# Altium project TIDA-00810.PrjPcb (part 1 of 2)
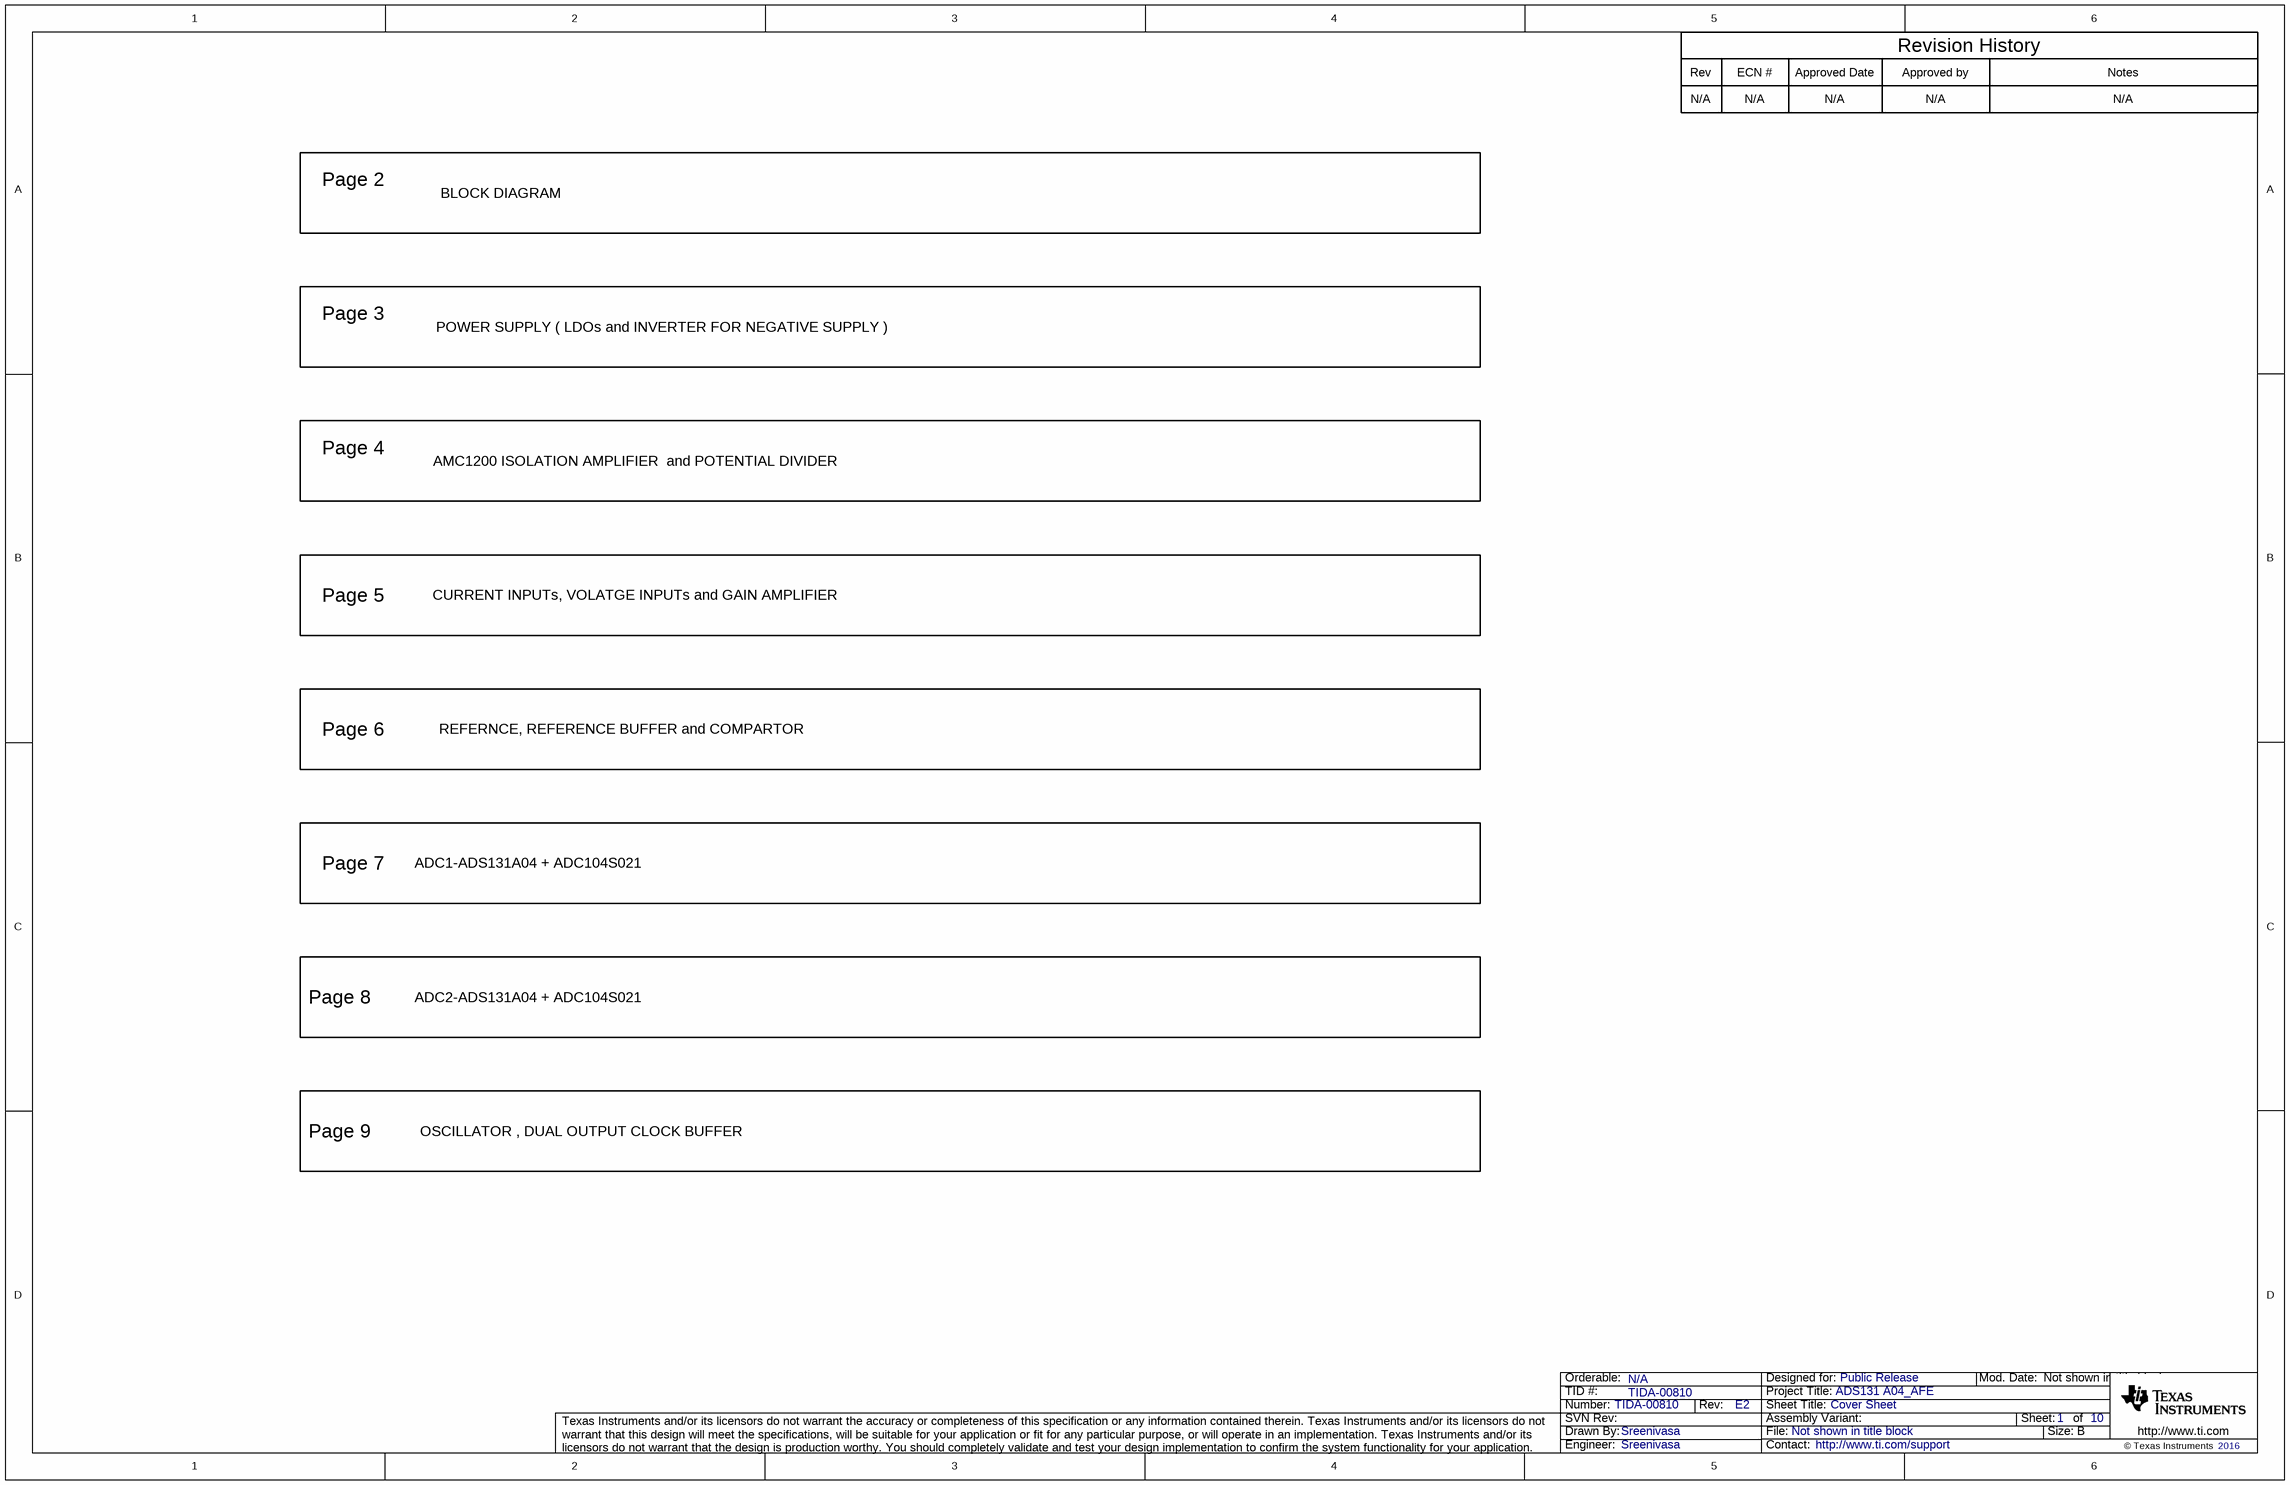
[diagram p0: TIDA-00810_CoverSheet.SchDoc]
TID: TIDA-00810; TechSupport: http://www.ti.com/support; SCH_Rev: E2; PRJ_Title: ADS131 A04_AFE; PRJ_Number: TIDA-00810; PRJ_Engineer: Sreenivasa; PRJ_Customer: Public Release; PCB_Rev: E2; PCB_Layout: Manjunath M; EVM_Orderable: N/A; CopyrightYear: 2016
10 sheets, 460 parts. Net scope: flat (ports and power ports of the same name join across sheets).
Board file: TIDA-00810-E2.PcbDoc
Sheets:
  TIDA-00810_CoverSheet.SchDoc
  TIDA-00810_Block Diagram.SchDoc
  TIDA-00810_POWER SUPPLY.SchDoc
  TIDA-00810_Isolation Amplifier.SchDoc
  TIDA-00810_OP-AMP.SchDoc
  TIDA-00810_Reference.SchDoc
  TIDA-00810_ADC1.SchDoc
  TIDA-00810_ADC2.SchDoc
  TIDA-00810_Buffer.SchDoc
  TIDA-00810_EVM_Hardware.SchDoc

## Sheet TIDA-00810_CoverSheet.SchDoc: Cover Sheet
size 431 x 279 mm; Date: Not shown in title block; ApprovedBy: Not shown in title block; CheckedBy: Not shown in title block; Author: Not shown in title block; CompanyName: Not shown in title block; DrawnBy: Sreenivasa; Engineer: Not shown in title block; Organization: Not shown in title block; Address1: Not shown in title block; Address2: Not shown in title block; Address3: Not shown in title block; Address4: Not shown in title block; DocumentNumber: 1; Revision: Use project parameter SCH_Rev; SheetNumber: 1; SheetTotal: 10; PageSetup: Record=PageOptions¦CenterHorizontal=True¦CenterVertical=True¦PrintScale=1.00¦XCorrection=1.00¦YCorrection=1.00¦PrintKind=0¦BorderSize=5000000¦LeftOffset=0¦BottomOffset=0¦Orientation=2¦PaperLength=1000¦PaperWidth=1000¦Scale=100¦PaperSource=15¦PrintQuality=-3¦MediaType=1¦DitherType=10¦PrintScaleMode=1¦PaperKind=Letter¦PaperIndex=1

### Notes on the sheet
- Rev
- N/A
- ECN #
- Approved Date
- Approved by
- Revision History
- Notes
- Page 2
- BLOCK DIAGRAM
- Page 3
- POWER SUPPLY ( LDOs and INVERTER FOR NEGATIVE SUPPLY )
- Page 4
- AMC1200 ISOLATION AMPLIFIER  and POTENTIAL DIVIDER
- Page 5
- CURRENT INPUTs, VOLATGE INPUTs and GAIN AMPLIFIER
- Page 6
- REFERNCE, REFERENCE BUFFER and COMPARTOR
- Page 7
- ADC1-ADS131A04 + ADC104S021
- Page 8
- ADC2-ADS131A04 + ADC104S021
- Page 9
- OSCILLATOR , DUAL OUTPUT CLOCK BUFFER

## Sheet TIDA-00810_Block Diagram.SchDoc: Cover Sheet
size 431 x 279 mm; Date: Not shown in title block; ApprovedBy: Not shown in title block; CheckedBy: Not shown in title block; Author: Not shown in title block; CompanyName: Not shown in title block; DrawnBy: Sreenivasa; Engineer: Not shown in title block; Organization: Not shown in title block; Address1: Not shown in title block; Address2: Not shown in title block; Address3: Not shown in title block; Address4: Not shown in title block; DocumentNumber: 1; Revision: Use project parameter SCH_Rev; SheetNumber: 2; SheetTotal: 10; PageSetup: Record=PageOptions¦CenterHorizontal=True¦CenterVertical=True¦PrintScale=1.00¦XCorrection=1.00¦YCorrection=1.00¦PrintKind=0¦BorderSize=5000000¦LeftOffset=0¦BottomOffset=0¦Orientation=2¦PaperLength=1000¦PaperWidth=1000¦Scale=100¦PaperSource=15¦PrintQuality=600¦MediaType=1¦DitherType=10¦PaperKind=Letter¦PrintScaleMode=1
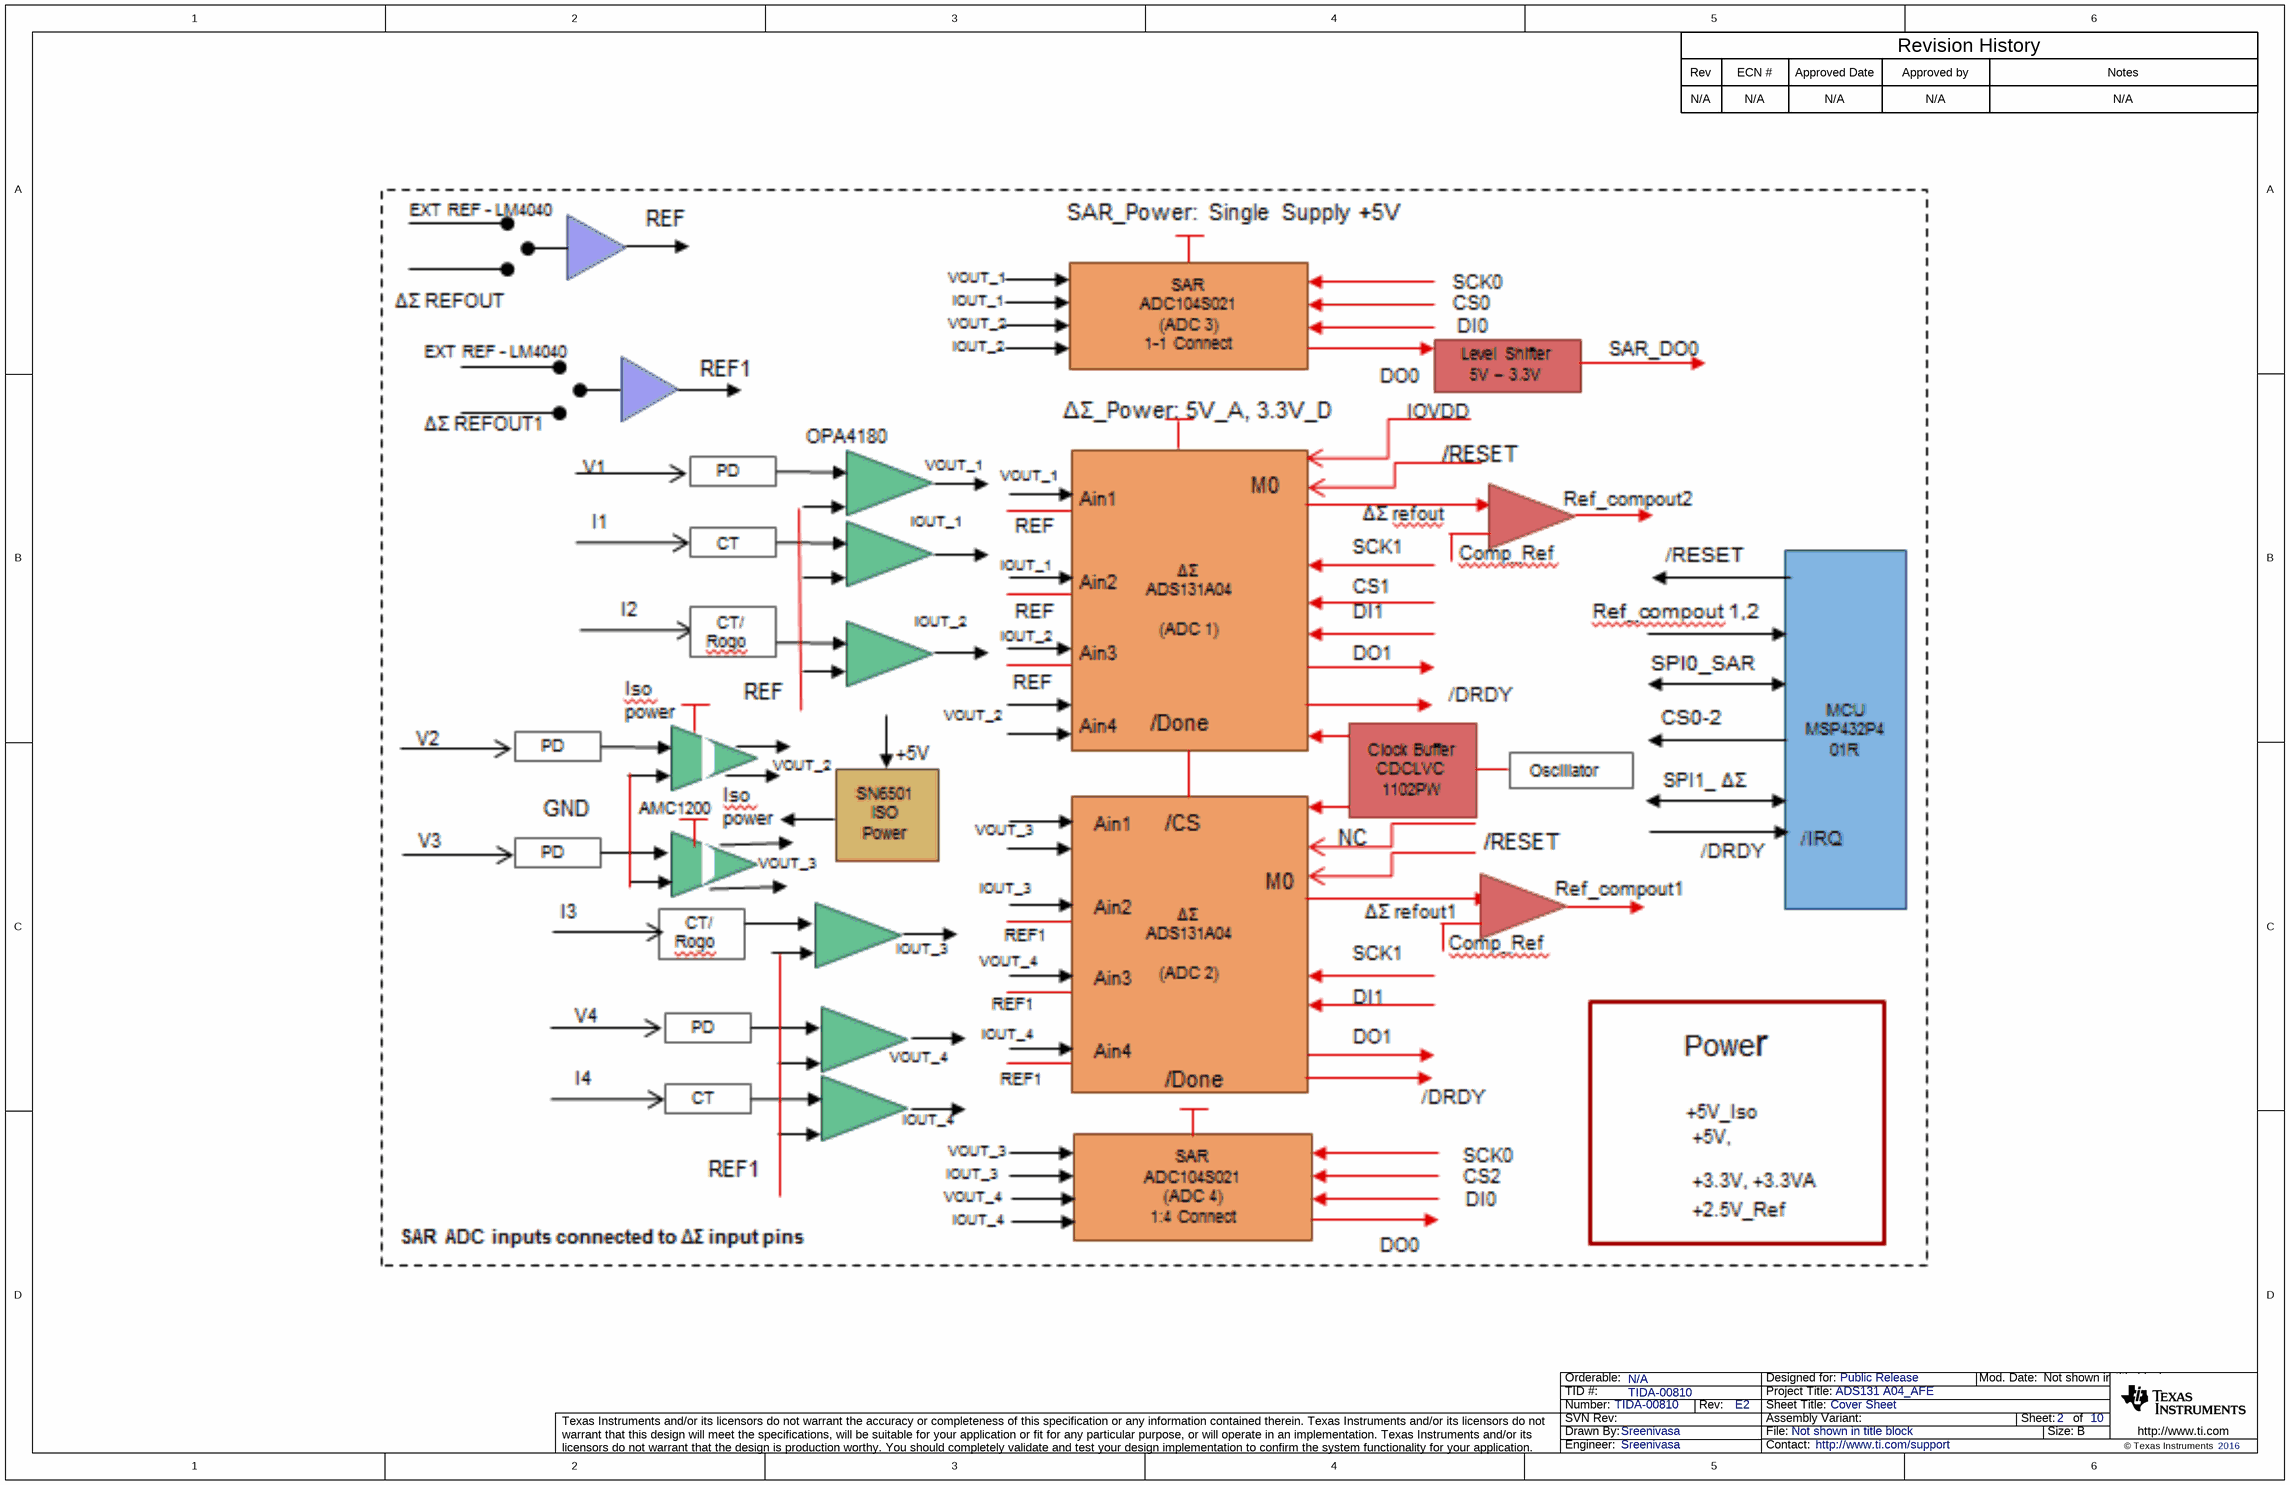
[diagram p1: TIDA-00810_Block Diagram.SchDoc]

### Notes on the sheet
- Rev
- N/A
- ECN #
- Approved Date
- Approved by
- Revision History
- Notes

## Sheet TIDA-00810_POWER SUPPLY.SchDoc: Power Supply
size 431 x 279 mm; Date: Not shown in title block; ApprovedBy: Not shown in title block; CheckedBy: Not shown in title block; Author: Not shown in title block; CompanyName: Not shown in title block; DrawnBy: Sreenivasa; Engineer: Not shown in title block; Organization: Not shown in title block; Address1: Not shown in title block; Address2: Not shown in title block; Address3: Not shown in title block; Address4: Not shown in title block; DocumentNumber: 1; Revision: Use project parameter SCH_Rev; SheetNumber: 3; SheetTotal: 10; PageSetup: Record=PageOptions¦CenterHorizontal=True¦CenterVertical=True¦PrintScale=1.00¦XCorrection=1.00¦YCorrection=1.00¦PrintKind=0¦BorderSize=5000000¦LeftOffset=0¦BottomOffset=0¦Orientation=2¦PaperLength=1000¦PaperWidth=1000¦Scale=100¦PaperSource=15¦PrintQuality=600¦MediaType=1¦DitherType=10¦PaperKind=Letter¦PrintScaleMode=1
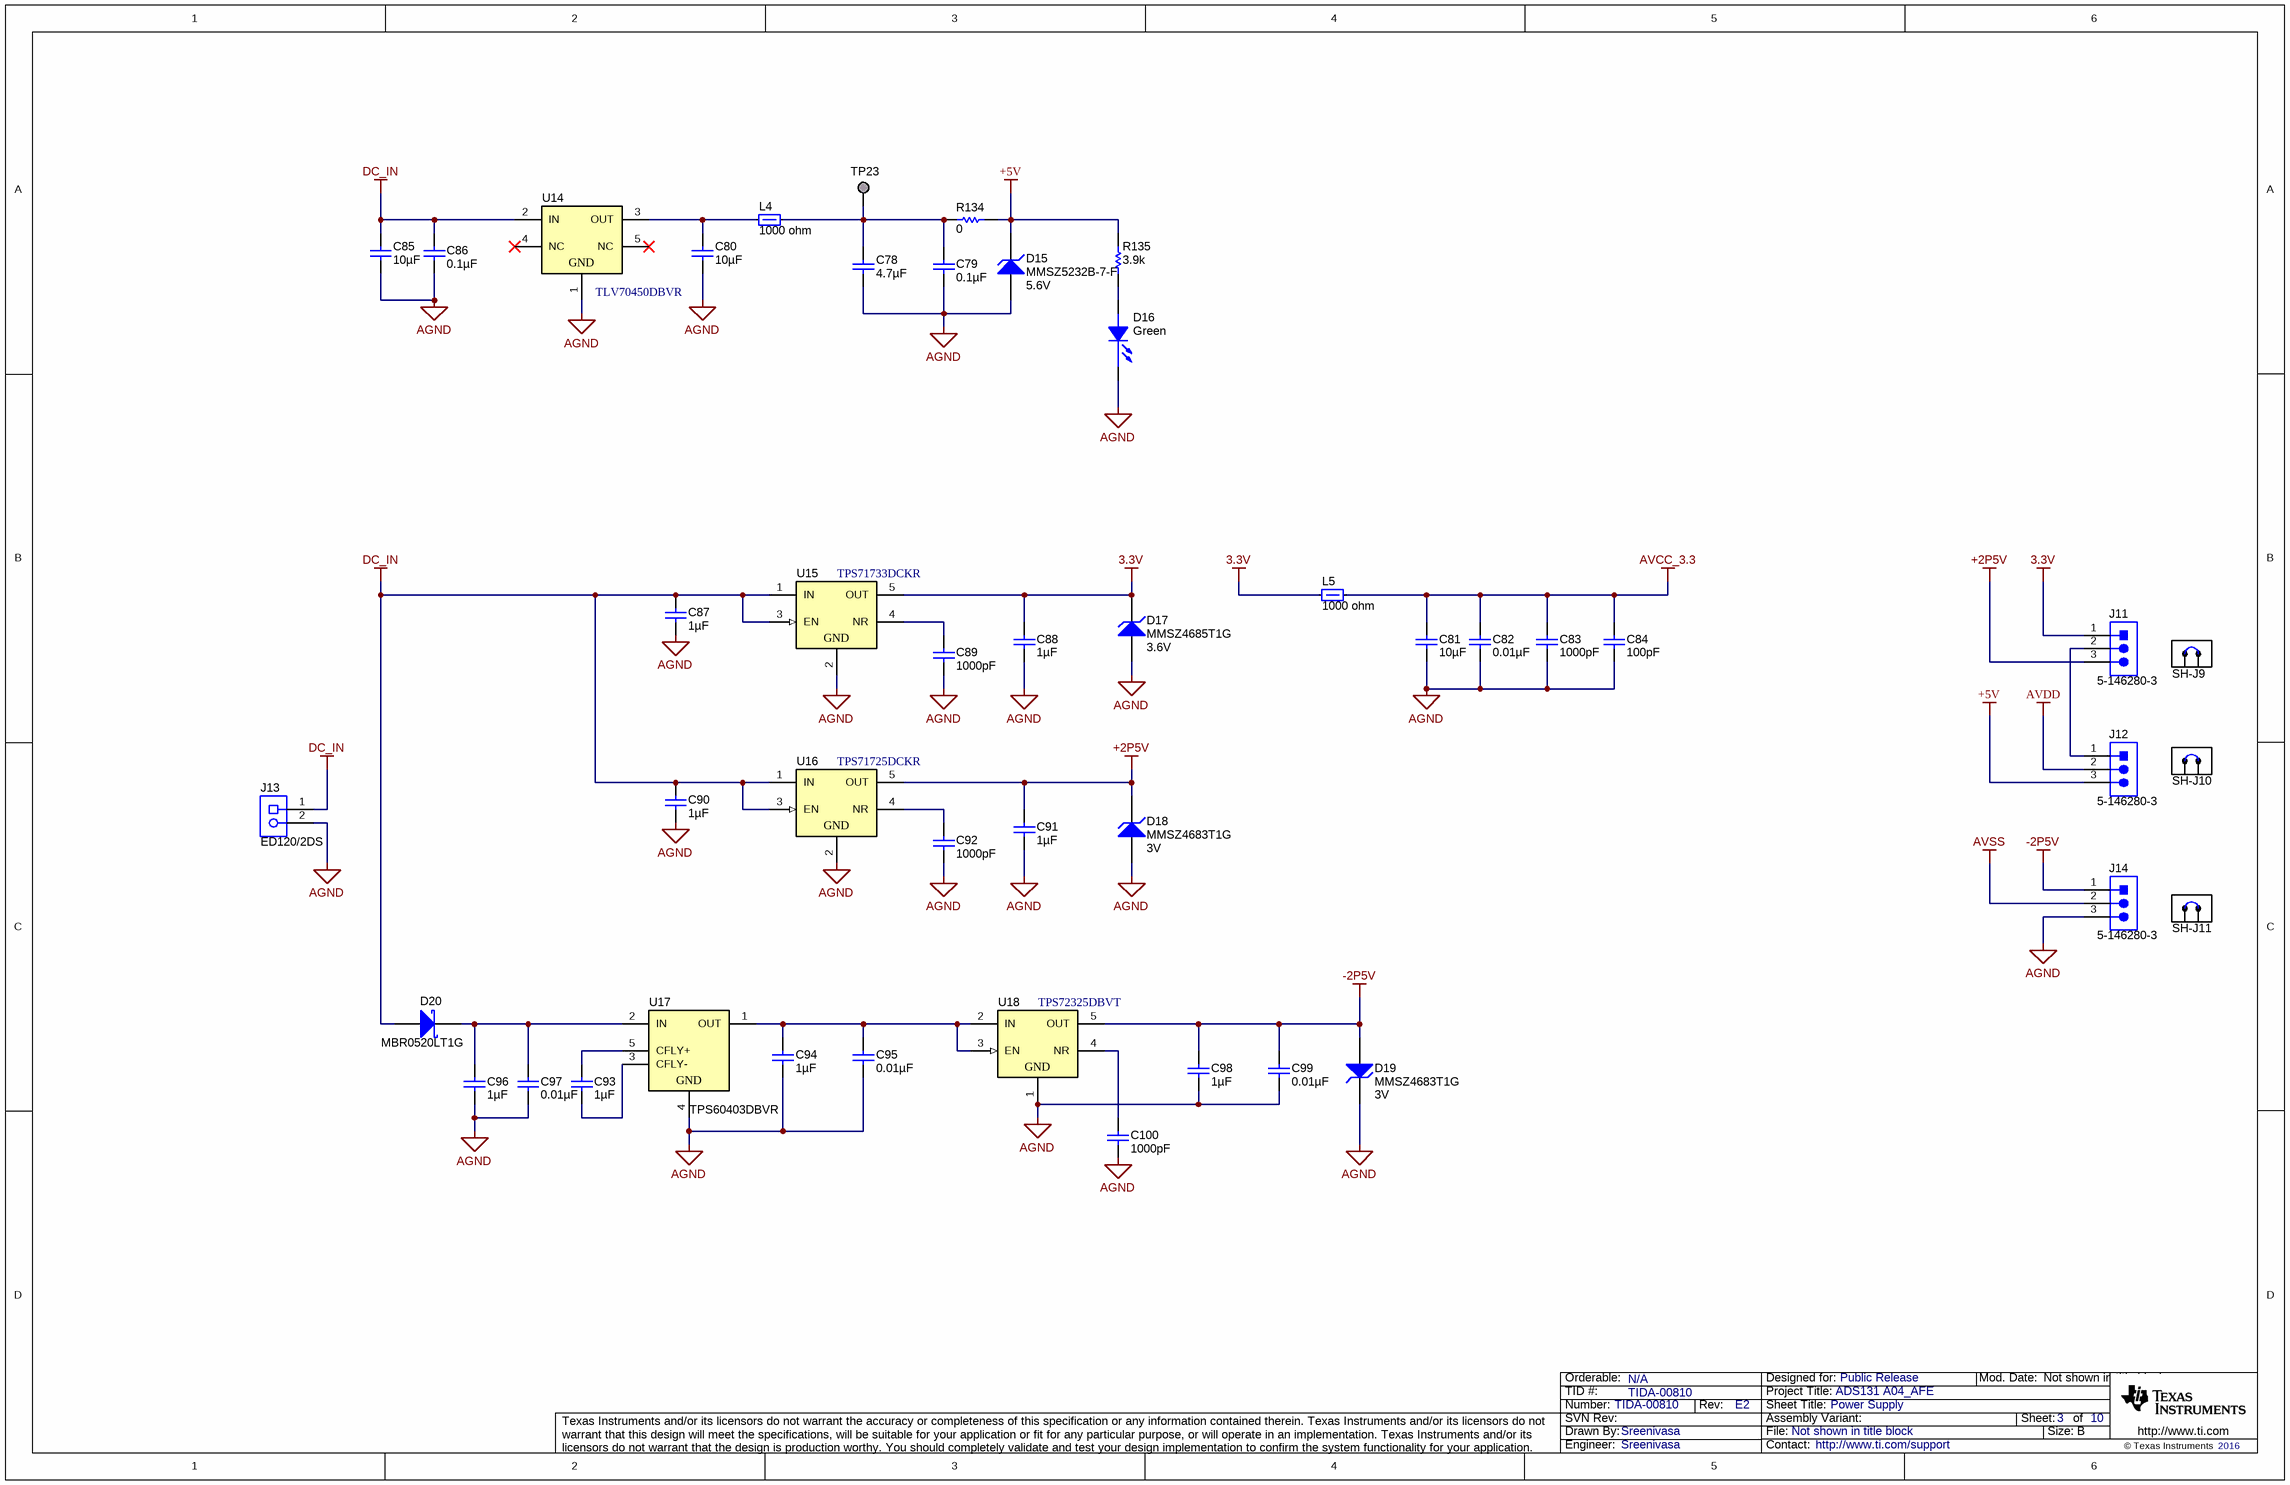
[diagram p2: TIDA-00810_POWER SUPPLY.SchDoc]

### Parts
C78  ValueDisplayed: 4.7µF  [0805_HV]
C79  ValueDisplayed: 0.1µF  [0603]
C80  ValueDisplayed: 10µF  [1210]
C81  ValueDisplayed: 10µF  [1206]  (hidden comment: GMK316AB7106KL)
C82  ValueDisplayed: 0.01µF  [0402]  (hidden comment: GCM155R71H103KA55D)
C83  ValueDisplayed: 1000pF  [0402]  (hidden comment: GRM155R61E102KA01D)
C84  ValueDisplayed: 100pF  [0402]  (hidden comment: CC0402KRX7R9BB101)
C85  ValueDisplayed: 10µF  [1210]
C86  ValueDisplayed: 0.1µF  [0603]
C87  ValueDisplayed: 1µF  [0603]  (hidden comment: GRM188R71E105KA12D)
C88  ValueDisplayed: 1µF  [0603]  (hidden comment: GRM188R71E105KA12D)
C89  ValueDisplayed: 1000pF  [0603]  (hidden comment: 06031C102JAT2A)
C90  ValueDisplayed: 1µF  [0603]  (hidden comment: GRM188R71E105KA12D)
C91  ValueDisplayed: 1µF  [0603]  (hidden comment: GRM188R71E105KA12D)
C92  ValueDisplayed: 1000pF  [0603]  (hidden comment: 06031C102JAT2A)
C93  ValueDisplayed: 1µF  [0603]  (hidden comment: GRM188R71E105KA12D)
C94  ValueDisplayed: 1µF  [0603]  (hidden comment: GRM188R71E105KA12D)
C95  ValueDisplayed: 0.01µF  [0603]  (hidden comment: 06031C103KAT2A)
C96  ValueDisplayed: 1µF  [0603]  (hidden comment: GRM188R71E105KA12D)
C97  ValueDisplayed: 0.01µF  [0603]  (hidden comment: 06031C103KAT2A)
C98  ValueDisplayed: 1µF  [0603]  (hidden comment: GRM188R71E105KA12D)
C99  ValueDisplayed: 0.01µF  [0603]  (hidden comment: 06031C103KAT2A)
C100  ValueDisplayed: 1000pF  [0603]  (hidden comment: 06031C102JAT2A)
D15  MMSZ5232B-7-F  value 5.6V  [SOD-123]
D16  value Green  [LED0603AA]
D17  MMSZ4685T1G  value 3.6V  [SOD-123]
D18  MMSZ4683T1G  value 3V  [SOD-123]
D19  MMSZ4683T1G  value 3V  [SOD-123]
D20  MBR0520LT1G  [SOD-123]
J11  5-146280-3  [TE_5-146280-3]
J12  5-146280-3  [TE_5-146280-3]
J13  ED120/2DS  [CONN_ED120-2DS]
J14  5-146280-3  [TE_5-146280-3]
L4  value 1000 ohm  [MMZ1608_095]  (hidden comment: MMZ1608B102CTA00)
L5  value 1000 ohm  [MMZ1608_095]  (hidden comment: MMZ1608B102CTA00)
R134  value 0  [0603]  (hidden comment: CRCW06030000Z0EA)
R135  value 3.9k  [0603]
SH-J9  881545-2  [TE_881545-2]  (value not drawn)  (mechanical)
SH-J10  881545-2  [TE_881545-2]  (value not drawn)  (mechanical)
SH-J11  881545-2  [TE_881545-2]  (value not drawn)  (mechanical)
TP23  Pogo Pad  [PogoPad]  (value not drawn)  (no BOM)
U14  TLV70450DBVR  [DBV0005A_N]
U15  TPS71733DCKR  [DCK0005A_N]
U16  TPS71725DCKR  [DCK0005A_N]
U17  TPS60403DBVR  [DBV0005A_N]
U18  TPS72325DBVT  [DBV0005A_N]

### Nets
3.3V: C88.1 D17.1(K) J11.1 L5.1 U15.5(OUT)
+2P5V: C91.1 D18.1(K) J11.3 U16.5(OUT)
+5V: D15.1(K) J12.3 R134.2 R135.2
-2P5V: C98.1 C99.1 D19.2(A) J14.1 U18.5(OUT)
AGND: C78.1 C79.2 C80.1 C81.2 C82.2 C83.2 C84.2 C85.1 C86.2 C87.2 C88.2 C89.2 C90.2 C91.2 C92.2 C94.2 C95.2 C96.2 C97.2 C98.2 C99.2 C100.2 D15.2(A) D16.1(C) D17.2(A) D18.2(A) D19.1(K) J13.2 J14.3 U14.1(GND) U15.2(GND) U16.2(GND) U17.4(GND) U18.1(GND)
AVCC_3.3: C81.1 C82.1 C83.1 C84.1 L5.2
AVDD: J12.2
AVSS: J14.2
DC_IN: C85.2 C86.1 C87.1 C90.1 D20.2(A) J13.1 U14.2(IN) U15.1(IN) U15.3(EN) U16.1(IN) U16.3(EN)
NetC78_2: C78.2 C79.1 L4.2 R134.1 TP23.1
NetC80_2: C80.2 L4.1 U14.3(OUT)
NetC89_1: C89.1 U15.4(NR)
NetC92_1: C92.1 U16.4(NR)
NetC93_1: C93.1 U17.5(CFLY+)
NetC93_2: C93.2 U17.3(CFLY-)
NetC94_1: C94.1 C95.1 U17.1(OUT) U18.2(IN) U18.3(EN)
NetC96_1: C96.1 C97.1 D20.1(K) U17.2(IN)
NetC100_1: C100.1 U18.4(NR)
NetD16_2: D16.2(A) R135.1
NetJ11_2: J11.2 J12.1

Not connected (* = marked no-connect by the designer): U14 4(NC)* 5(NC)*

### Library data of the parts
C78 = C2012X5R1H475K125AB: 4.7µF ±10% 50V X5R Ceramic Capacitor -55°C ~ 85°C; PartNumber: GRM21BR61H475KE51L; Manufacturer: TDK; Polarized: N; Value: 4.7uF; U/M: EA; Cap_F: 0.0000047; Tolerance_%: 10; Value1: Unknown; VDC_V: 50; TaMin_C: -55; TaMax_C: 85; Cap_Case: 0805
C79 C86 = C0603C104K5RACTU: CAP, CERM, 0.1uF, 50V, +/-10%, X7R, 0603; Manufacturer: Kemet; Polarized: N; CompType: Capacitor; U/M: EA; Cap_F: 0.0000001; Tolerance_%: 10; Value1: Unknown; VDC_V: 50; TaMin_C: -55; TaMax_C: 125
C80 C85 = GMK325AB7106MM-T: CAP, CERM, 10uF, 35V, +/-20%, X7R, 1210; Manufacturer: Taiyo Yuden; Polarized: N; CompType: Capacitor; U/M: EA; Cap_F: 0.00001; Tolerance_%: 20; Value1: Unknown; VDC_V: 35; TaMin_C: -55; TaMax_C: 125
C81 = GMK316AB7106KL: CAP, CERM, 10uF, 35V, +/-10%, X7R, 1206; Manufacturer: Taiyo Yuden; Polarized: N; CompType: Capacitor; U/M: EA; Cap_F: 0.00001; Tolerance_%: 10; Value1: Unknown; VDC_V: 35; TaMin_C: -55; TaMax_C: 125
C82 = GCM155R71H103KA55D: CAP, CERM, 0.01uF, 50V, +/-10%, C0G/NP0, 0402; Manufacturer: MuRata; Polarized: N; CompType: Capacitor; U/M: EA; Cap_F: 0.00000001; Tolerance_%: 10; Value1: Unknown; VDC_V: 50; TaMin_C: -55; TaMax_C: 125
C83 = GRM155R61E102KA01D: CAP, CERM, 1000pF, 25V, +/-10%, X5R, 0402; Manufacturer: MuRata; Polarized: N; CompType: Capacitor; U/M: EA; Cap_F: 0.000000001; Tolerance_%: 10; Value1: Unknown; VDC_V: 25; TaMin_C: -55; TaMax_C: 85
C84 = CC0402KRX7R9BB101: CAP, CERM, 100pF, 50V, +/-10%, X7R, 0402; Manufacturer: Yageo America; Polarized: N; CompType: Capacitor; U/M: EA; Cap_F: 0.0000000001; Tolerance_%: 10; Value1: Unknown; VDC_V: 50; TaMin_C: -55; TaMax_C: 125
C87 C88 C90 C91 C93 C94 C96 C98 = GRM188R71E105KA12D: CAP, CERM, 1 µF, 25 V, +/- 10%, X7R, 0603; Manufacturer: MuRata; Polarized: N; CompType: Capacitor; Value: 1uF; U/M: EA; Cap_F: 0.000001; Tolerance_%: 10; Value1: Unknown; VDC_V: 25; Value2: 25V; TaMin_C: -55; TaMax_C: 125; AEC Category: Q200
C89 C92 C100 = 06031C102JAT2A: CAP, CERM, 1000 pF, 100 V, +/- 5%, X7R, 0603; Manufacturer: AVX; Polarized: N; CompType: Capacitor; Value: 1000pF; U/M: EA; Cap_F: 0.000000001; Tolerance_%: 5; ESR_ohm: 0.276; Value1: 0.276 ohm; VDC_V: 100; Value2: 100V; TaMin_C: -55; TaMax_C: 125; AEC Category: Q200
C95 C97 C99 = 06031C103KAT2A: CAP, CERM, 0.01 µF, 100 V, +/- 10%, X7R, 0603; Manufacturer: AVX; Polarized: N; CompType: Capacitor; Value: 0.01uF; U/M: EA; Cap_F: 0.00000001; Tolerance_%: 10; ESR_ohm: 0.098; Value1: 0.098 ohm; VDC_V: 100; Value2: 100V; TaMin_C: -55; TaMax_C: 125; AEC Category: Q200
D15 = MMSZ5232B-7-F: Diode, Zener, 5.6 V, 500 mW, SOD-123; Manufacturer: Diodes Inc.; SymbolCreator: a0412235; U/M: EA; Power_W: 0.5; Vz_V: 5.6; Value1: 0.5W; RJA_CperW: 350; AEC Category: Q101
D16 = LED_LG L29K-G2J1-24-Z: LED SmartLED Green 570NM; Manufacturer: OSRAM; SymbolCreator: x0120606
D17 = MMSZ4685T1G: Diode, Zener, 3.6 V, 500 mW, SOD-123; Manufacturer: ON Semiconductor; SymbolCreator: a0412235; U/M: EA; Power_W: 0.5; Vz_V: 3.6; Value1: 0.5W; RJA_CperW: 340; AEC Category: Q101
D18 D19 = MMSZ4683T1G: Diode, Zener, 3 V, 500 mW, SOD-123; Manufacturer: ON Semiconductor; SymbolCreator: a0412235; U/M: EA; Power_W: 0.5; Vz_V: 3; Value1: 0.5W; RJA_CperW: 340; AEC Category: Q101
D20 = MBR0520LT1G: Diode, Schottky, 20 V, 0.5 A, SOD-123; Manufacturer: ON Semiconductor; U/M: EA; Vf_V: 0.385; Value: 20V; Value1: 0.5A; Value2: 0.385V; Io_A: 0.5; Vr_V: 20; TJmax_C: 125; RJC_CperW: 150; AEC Category: Q101
J11 J12 J14 = 5-146280-3: Header, 2.54mm, 3x1, Gold, TH; Manufacturer: TE Connectivity; SymbolCreator: a0799628; Pitch_mm: 2.54; Gender: Male; Shrouded: N; Row_Count: 1
J13 = ED120/2DS: TERMINAL BLOCK 5.08MM VERT 2POS, TH; Manufacturer: On-Shore Technology; SymbolCreator: a0412235; U/M: EA
L4 L5 = MMZ1608B102CTA00: Ferrite Bead, 1000 ohm @ 100 MHz, 0.3 A, 0603; Manufacturer: TDK; Imax_A: 0.3; DCR_ohm: 0.6; Value1: 0.6 ohm; Value2: 0.3A; ZTyp@100MHz_Ohm: 1000
R134 = CRCW06030000Z0EA: RES, 0 ohm, 5%, 0.1W, 0603; Manufacturer: Vishay-Dale; CompType: Resistor; Value_Code: 0000; Tolerance_%: 5; Power_W: 0.1; VDC_V: 75; TempCo: 200 ppm/C; EIA_Code: E24; U/M: EA
R135 = CRCW06033K90JNEA: RES, 3.9k ohm, 5%, 0.1W, 0603; Manufacturer: Vishay-Dale; CompType: Resistor; Res_ohm: 3900; Value_Code: 3k90; Tolerance_%: 5; Power_W: 0.1; VDC_V: 75; TempCo: 200 ppm/C; EIA_Code: E24; U/M: EA
SH-J9-SH-J11 = 881545-2: Shunt, 100mil, Gold plated, Black; Manufacturer: TE Connectivity
TP23 = PogoPad: Pad for Pogo Pin Connector; SymbolCreator: codlsc
U14 = TLV70450DBVR: Single Output LDO, 150 mA, Fixed 5 V Output, 2.5 to 24 V Input, with Ultra-Low IQ, 5-pin SOT-23 (DBV), -40 to 125 degC, Green (RoHS & no Sb/Br); Manufacturer: Texas Instruments; Alternate PartNumber: Equivalent; Accuracy(%): 2; Fixed Output Options(V): 5; Iout(Max)(A): 0.15; Iq(Typ)(mA): 0.003; SubFamily: Single Channel LDO; Vdo(Typ)(mV): 400; Vin(Max)(V): 24; Vin(Min)(V): 2.5
U15 = TPS71733DCKR: Single Output High PSRR LDO, 150 mA, Fixed 3.3 V Output, 2.5 to 6.5 V Input, with Low IQ, 5-pin SC70 (DCK), -40 to 85 degC, Green (RoHS & no Sb/Br); Manufacturer: Texas Instruments; Alternate PartNumber: Equivalent; Accuracy(%): 3; Fixed Output Options(V): 3.3; Iout(Max)(A): 0.15; Iq(Typ)(mA): 0.05; SubFamily: Single Channel LDO; Vdo(Typ)(mV): 170; Vin(Max)(V): 6.5; Vin(Min)(V): 2.5
U16 = TPS71725DCKR: Single Output High PSRR LDO, 150 mA, Fixed 2.5 V Output, 2.5 to 6.5 V Input, with Low IQ, 5-pin SC70 (DCK), -40 to 85 degC, Green (RoHS & no Sb/Br); Manufacturer: Texas Instruments; Alternate PartNumber: Equivalent; Accuracy(%): 3; Fixed Output Options(V): 2.5; Iout(Max)(A): 0.15; Iq(Typ)(mA): 0.05; SubFamily: Single Channel LDO; Vdo(Typ)(mV): 170; Vin(Max)(V): 6.5
U17 = TPS60403DBVR: -1.8 to -5.25 V, Inverting Charge Pump Regulator, 60 mA, 1.8 to 5.25 V Input with 2-Cell Alkaline / Nixx Input, -40 to 85 degC, 5-pin SOT23 (DBV5), Green (RoHS & no Sb/Br); Manufacturer: Texas Instruments; Alternate PartNumber: Equivalent; 2-Cell Alkaline/Nixx Input: TRUE; Efficiency(Typ)(%): 99; Iout(Max)(A): 0.06; Iq(Typ)(mA): 0.425; Switching Frequency(Max)(kHz): 300; Topology: Inverting Buck/Boost; Vin(Max)(V): 5.25; Vin(Min)(V): 1.8
U18 = TPS72325DBVT: Single Output High PSRR LDO, 200 mA, Fixed -2.5 V Output, -10 to -2.7 V Input, 5-pin SOT-23 (DBV), -40 to 125 degC, Green (RoHS & no Sb/Br); Manufacturer: Texas Instruments; Alternate PartNumber: Equivalent; Accuracy(%): 2; Iout(Max)(A): 0.2; Iq(Typ)(mA): 0.13; SubFamily: Single Channel LDO; Vdo(Typ)(mV): 280

## Sheet TIDA-00810_Isolation Amplifier.SchDoc: Isolation Amplifier
size 431 x 279 mm; Date: Not shown in title block; ApprovedBy: Not shown in title block; CheckedBy: Not shown in title block; Author: Not shown in title block; CompanyName: Not shown in title block; DrawnBy: Sreenivasa; Engineer: Not shown in title block; Organization: Not shown in title block; Address1: Not shown in title block; Address2: Not shown in title block; Address3: Not shown in title block; Address4: Not shown in title block; DocumentNumber: 1; Revision: Use project parameter SCH_Rev; SheetNumber: 4; SheetTotal: 10; PageSetup: Record=PageOptions¦CenterHorizontal=True¦CenterVertical=True¦PrintScale=1.00¦XCorrection=1.00¦YCorrection=1.00¦PrintKind=0¦BorderSize=5000000¦LeftOffset=0¦BottomOffset=0¦Orientation=2¦PaperLength=1000¦PaperWidth=1000¦Scale=100¦PaperSource=15¦PrintQuality=600¦MediaType=1¦DitherType=10¦PaperKind=Letter¦PrintScaleMode=1
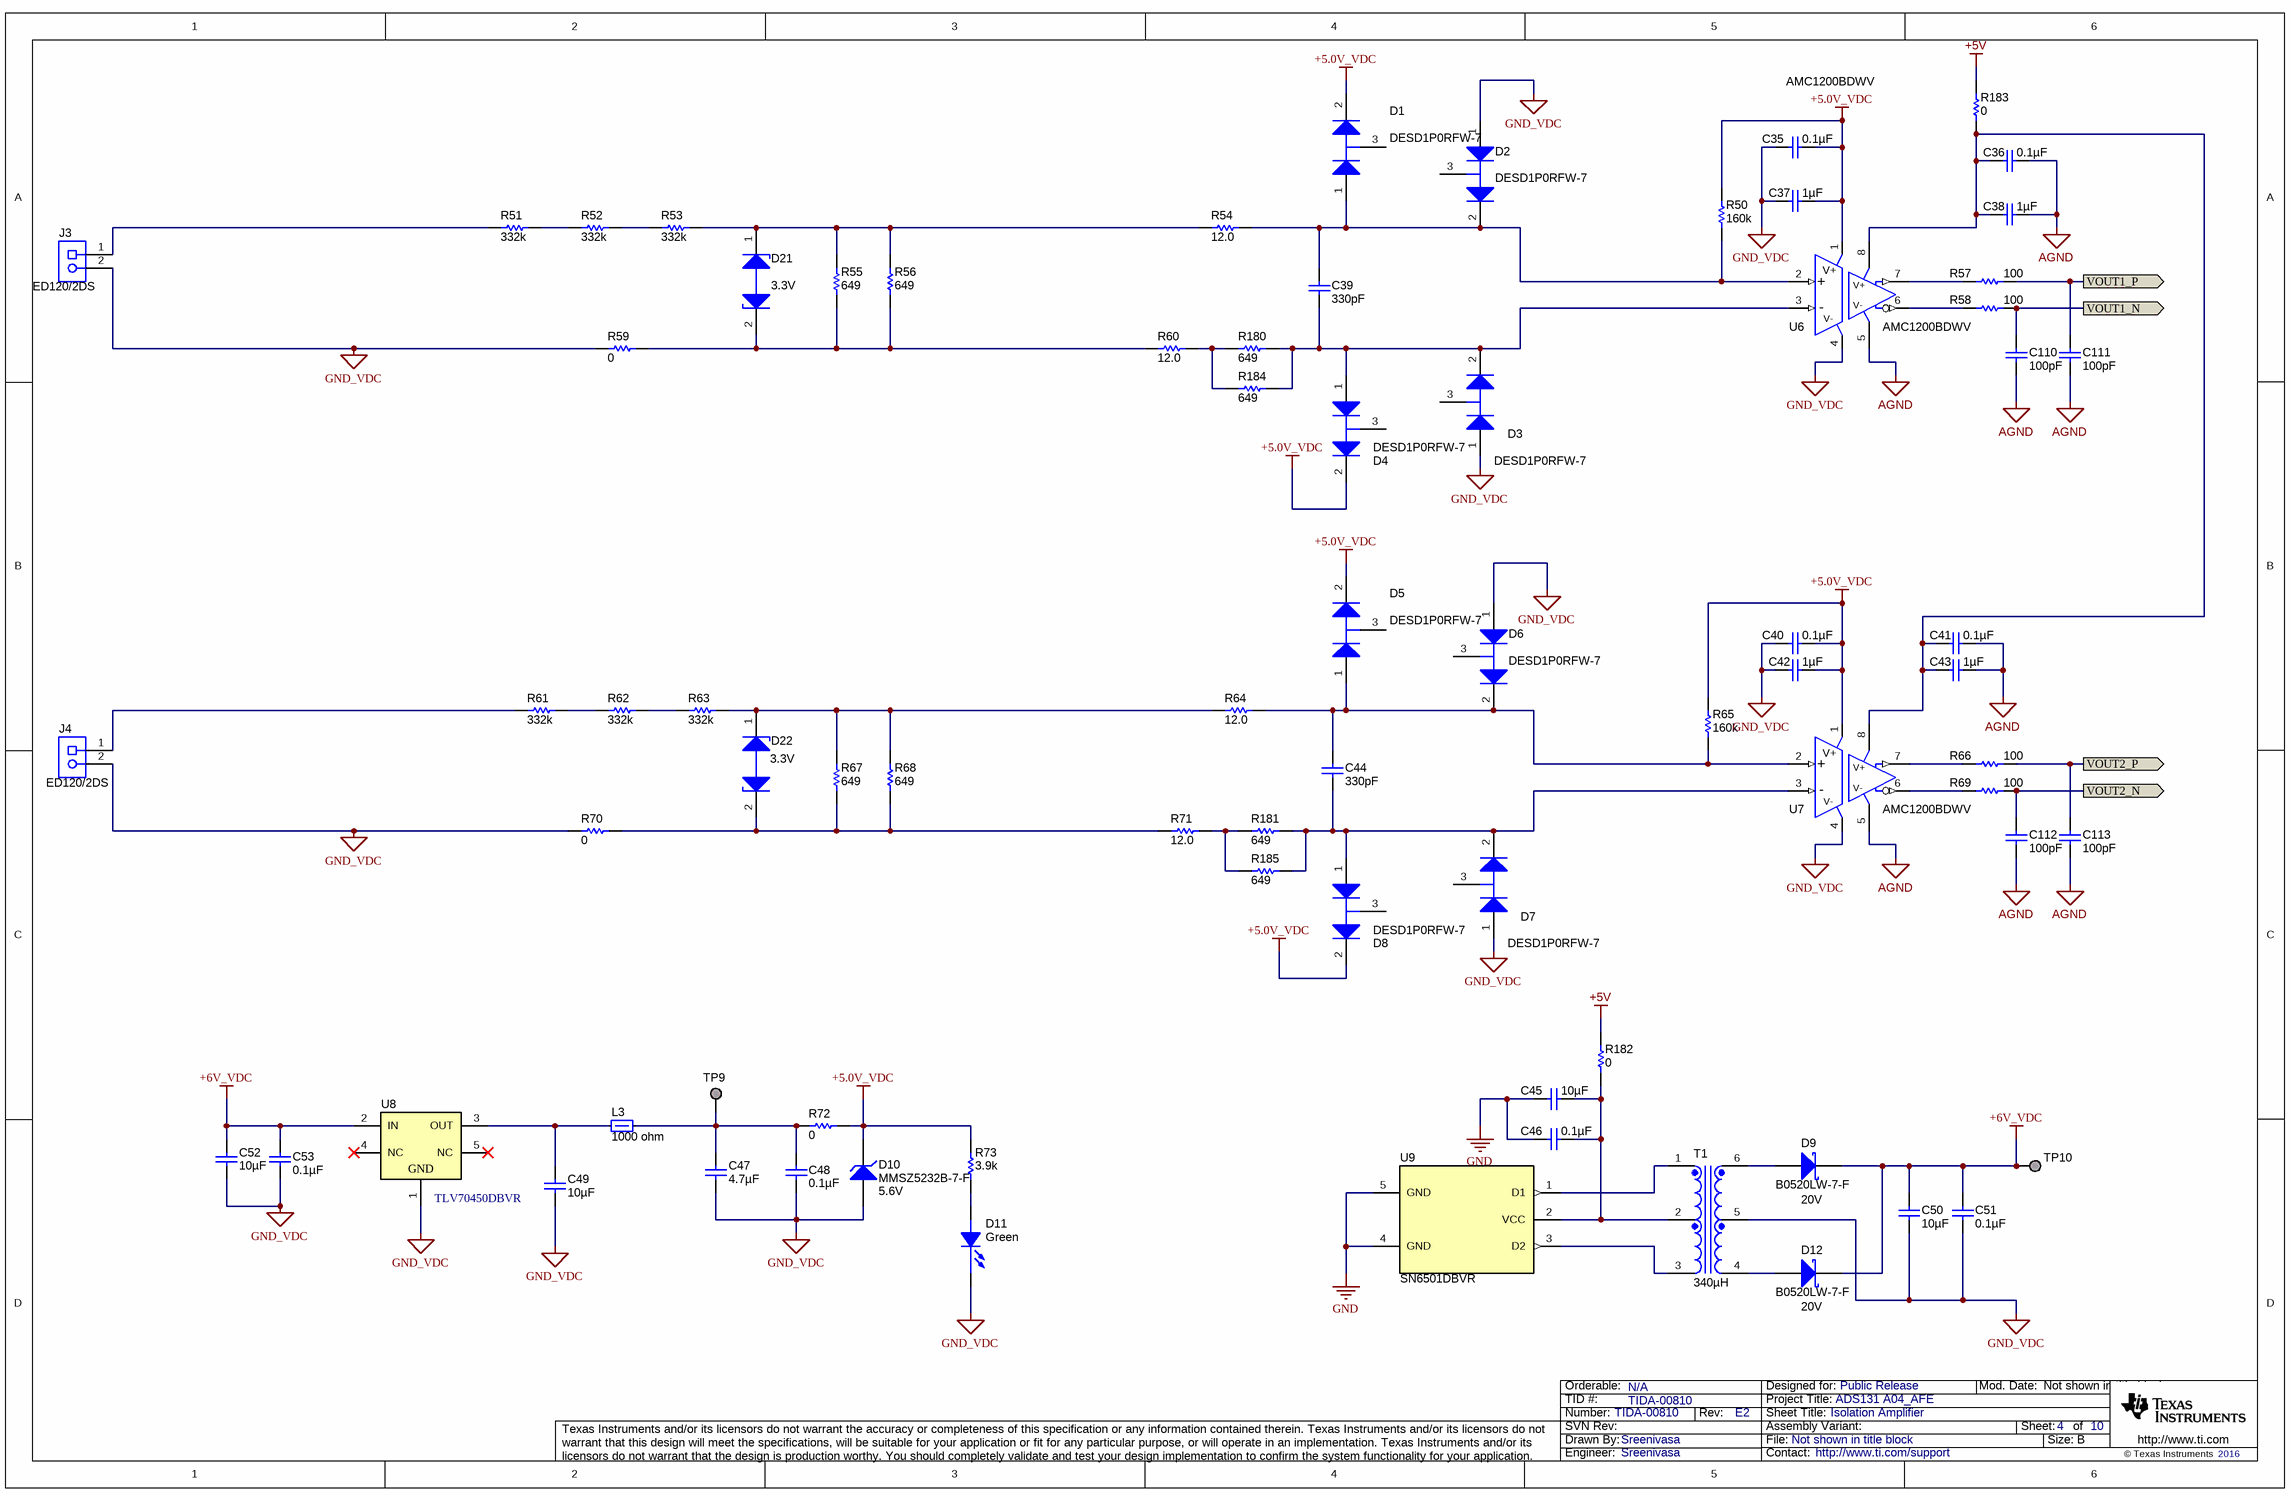
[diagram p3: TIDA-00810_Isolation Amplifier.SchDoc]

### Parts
C35  ValueDisplayed: 0.1µF  [0603]
C36  ValueDisplayed: 0.1µF  [0603]
C37  ValueDisplayed: 1µF  [0603]  (hidden comment: GRM188R71C105KA12D)
C38  ValueDisplayed: 1µF  [0603]  (hidden comment: GRM188R71C105KA12D)
C39  ValueDisplayed: 330pF  [0805_HV]  (hidden comment: 08055A331KAT2A)
C40  ValueDisplayed: 0.1µF  [0603]
C41  ValueDisplayed: 0.1µF  [0603]
C42  ValueDisplayed: 1µF  [0603]  (hidden comment: GRM188R71C105KA12D)
C43  ValueDisplayed: 1µF  [0603]  (hidden comment: GRM188R71C105KA12D)
C44  ValueDisplayed: 330pF  [0805_HV]  (hidden comment: 08055A331KAT2A)
C45  ValueDisplayed: 10µF  [1210]
C46  ValueDisplayed: 0.1µF  [0603]
C47  ValueDisplayed: 4.7µF  [0805_HV]
C48  ValueDisplayed: 0.1µF  [0603]
C49  ValueDisplayed: 10µF  [1210]
C50  ValueDisplayed: 10µF  [1210]
C51  ValueDisplayed: 0.1µF  [0603]
C52  ValueDisplayed: 10µF  [1210]
C53  ValueDisplayed: 0.1µF  [0603]
C110  ValueDisplayed: 100pF  [0603]  (hidden comment: 06033C101KAT2A)
C111  ValueDisplayed: 100pF  [0603]  (hidden comment: 06033C101KAT2A)
C112  ValueDisplayed: 100pF  [0603]  (hidden comment: 06033C101KAT2A)
C113  ValueDisplayed: 100pF  [0603]  (hidden comment: 06033C101KAT2A)
D1  value DESD1P0RFW-7  [SOT-323]
D2  value DESD1P0RFW-7  [SOT-323]
D3  value DESD1P0RFW-7  [SOT-323]
D4  value DESD1P0RFW-7  [SOT-323]
D5  value DESD1P0RFW-7  [SOT-323]
D6  value DESD1P0RFW-7  [SOT-323]
D7  value DESD1P0RFW-7  [SOT-323]
D8  value DESD1P0RFW-7  [SOT-323]
D9  B0520LW-7-F  value 20V  [SOD-123]
D10  MMSZ5232B-7-F  value 5.6V  [SOD-123]
D11  value Green  [LED0603AA]
D12  B0520LW-7-F  value 20V  [SOD-123]
D21  value 3.3V  [DIO_SOD323]  (hidden comment: PESD3V3L1BA)
D22  value 3.3V  [DIO_SOD323]  (hidden comment: PESD3V3L1BA)
J3  ED120/2DS  [CONN_ED120-2DS]
J4  ED120/2DS  [CONN_ED120-2DS]
L3  value 1000 ohm  [MMZ1608_095]  (hidden comment: MMZ1608B102CTA00)
R50  ValueDisplayed: 160k  [0603]  (hidden comment: CRCW0603160KFKEA)
R51  ValueDisplayed: 332k  [1206]  (hidden comment: ERJ-8ENF3323V)
R52  ValueDisplayed: 332k  [1206]  (hidden comment: ERJ-8ENF3323V)
R53  ValueDisplayed: 332k  [1206]  (hidden comment: ERJ-8ENF3323V)
R54  ValueDisplayed: 12.0  [0603]  (hidden comment: RC0603FR-0712RL)
R55  ValueDisplayed: 649  [0603]  (hidden comment: CRCW0603649RFKEA)
R56  ValueDisplayed: 649  [0603]  (hidden comment: CRCW0603649RFKEA)
R57  value 100  [0603]  (hidden comment: CRCW0603100RFKEA)
R58  value 100  [0603]  (hidden comment: CRCW0603100RFKEA)
R59  value 0  [0805_HV]  (hidden comment: CRCW08050000Z0EA)
R60  ValueDisplayed: 12.0  [0603]  (hidden comment: RC0603FR-0712RL)
R61  ValueDisplayed: 332k  [1206]  (hidden comment: ERJ-8ENF3323V)
R62  ValueDisplayed: 332k  [1206]  (hidden comment: ERJ-8ENF3323V)
R63  ValueDisplayed: 332k  [1206]  (hidden comment: ERJ-8ENF3323V)
R64  ValueDisplayed: 12.0  [0603]  (hidden comment: RC0603FR-0712RL)
R65  ValueDisplayed: 160k  [0603]  (hidden comment: CRCW0603160KFKEA)
R66  value 100  [0603]  (hidden comment: CRCW0603100RFKEA)
R67  ValueDisplayed: 649  [0603]  (hidden comment: CRCW0603649RFKEA)
R68  ValueDisplayed: 649  [0603]  (hidden comment: CRCW0603649RFKEA)
R69  value 100  [0603]  (hidden comment: CRCW0603100RFKEA)
R70  value 0  [0805_HV]  (hidden comment: CRCW08050000Z0EA)
R71  ValueDisplayed: 12.0  [0603]  (hidden comment: RC0603FR-0712RL)
R72  value 0  [0603]  (hidden comment: CRCW06030000Z0EA)
R73  value 3.9k  [0603]
R180  ValueDisplayed: 649  [0603]  (hidden comment: CRCW0603649RFKEA)
R181  ValueDisplayed: 649  [0603]  (hidden comment: CRCW0603649RFKEA)
R182  value 0  [0603]  (hidden comment: CRCW06030000Z0EA)
R183  value 0  [0805_HV]  (hidden comment: CRCW08050000Z0EA)
R184  ValueDisplayed: 649  [0603]  (hidden comment: CRCW0603649RFKEA)
R185  ValueDisplayed: 649  [0603]  (hidden comment: CRCW0603649RFKEA)
T1  ValueDisplayed: 340µH  [Wurth_750313638]  (hidden comment: 750313638)
TP9  Pogo Pad  [PogoPad]  (value not drawn)  (no BOM)
TP10  Pogo Pad  [PogoPad]  (value not drawn)  (no BOM)
U6  AMC1200BDWV  [DWV0008A]
U7  AMC1200BDWV  [DWV0008A]
U8  TLV70450DBVR  [DBV0005A_N]
U9  SN6501DBVR  [DBV0005A_N]

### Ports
VOUT1_N (out), VOUT1_P (out), VOUT2_N (out), VOUT2_P (out)

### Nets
+5.0V_VDC: C35.1 C37.2 C40.1 C42.2 D1.2(K) D4.2(K) D5.2(K) D8.2(K) D10.1(K) R50.2 R65.2 R72.2 R73.2 U6.1(VDD1) U7.1(VDD1)
+5V: R182.2 R183.2
+6V_VDC: C50.1 C51.1 C52.2 C53.1 D9.1(K) D12.1(K) TP10.1 U8.2(IN)
AGND: C36.1 C38.2 C41.1 C43.2 C110.2 C111.2 C112.2 C113.2 U6.5(GND2) U7.5(GND2)
GND: C45.1 C46.1 U9.4(GND) U9.5(GND)
GND_VDC: C35.2 C37.1 C40.2 C42.1 C47.1 C48.2 C49.1 C50.2 C51.2 C52.1 C53.2 D2.1(A) D3.1(A) D6.1(A) D7.1(A) D10.2(A) D11.1(C) J3.2 J4.2 R59.1 R70.1 T1.5 U6.4(GND1) U7.4(GND1) U8.1(GND)
VOUT1_N: C110.1 R58.2 ; port VOUT1_N
VOUT1_P: C111.1 R57.2 ; port VOUT1_P
VOUT2_N: C112.1 R69.2 ; port VOUT2_N
VOUT2_P: C113.1 R66.2 ; port VOUT2_P
NetC36_2: C36.2 C38.1 C41.2 C43.1 R183.1 U6.8(VDD2) U7.8(VDD2)
NetC39_1: C39.1 D1.1(A) D2.2(K) R50.1 R54.2 U6.2(VINP)
NetC39_2: C39.2 D3.2(K) D4.1(A) R180.1 R184.1 U6.3(VINN)
NetC44_1: C44.1 D5.1(A) D6.2(K) R64.2 R65.1 U7.2(VINP)
NetC44_2: C44.2 D7.2(K) D8.1(A) R181.1 R185.1 U7.3(VINN)
NetC45_2: C45.2 C46.2 R182.1 T1.2 U9.2(VCC)
NetC47_2: C47.2 C48.1 L3.2 R72.1 TP9.1
NetC49_2: C49.2 L3.1 U8.3(OUT)
NetD9_2: D9.2(A) T1.6
NetD11_2: D11.2(A) R73.1
NetD12_2: D12.2(A) T1.4
NetD21_1: D21.1(K) R53.2 R54.1 R55.2 R56.2
NetD21_2: D21.2(K) R55.1 R56.1 R59.2 R60.1
NetD22_1: D22.1(K) R63.2 R64.1 R67.2 R68.2
NetD22_2: D22.2(K) R67.1 R68.1 R70.2 R71.1
NetJ3_1: J3.1 R51.1
NetJ4_1: J4.1 R61.1
NetR51_2: R51.2 R52.1
NetR52_2: R52.2 R53.1
NetR57_1: R57.1 U6.7(VOUTP)
NetR58_1: R58.1 U6.6(VOUTN)
NetR60_2: R60.2 R180.2 R184.2
NetR61_2: R61.2 R62.1
NetR62_2: R62.2 R63.1
NetR66_1: R66.1 U7.7(VOUTP)
NetR69_1: R69.1 U7.6(VOUTN)
NetR71_2: R71.2 R181.2 R185.2
NetT1_1: T1.1 U9.1(D1)
NetT1_3: T1.3 U9.3(D2)

Not connected (* = marked no-connect by the designer): D1 3(C); D2 3(C); D3 3(C); D4 3(C); D5 3(C); D6 3(C); D7 3(C); D8 3(C); U8 4(NC)* 5(NC)*

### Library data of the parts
C35 C36 C40 C41 = 06033C104JAT2A: CAP, CERM, 0.1uF, 25V, +/-5%, X7R, 0603; Manufacturer: AVX; Polarized: N; CompType: Capacitor; U/M: EA; Cap_F: 0.0000001; Tolerance_%: 5; ESR_Ohm: 0.05; Value1: 0.05 ohm; VDC_V: 25; TaMin_C: -55; TaMax_C: 125
C37 C38 C42 C43 = GRM188R71C105KA12D: CAP, CERM, 1 µF, 16 V, +/- 10%, X7R, 0603; Manufacturer: MuRata; Polarized: N; CompType: Capacitor; Value: 1uF; U/M: EA; Cap_F: 0.000001; Tolerance_%: 10; ESR_ohm: 0.011; Value1: 0.011 ohm; VDC_V: 16; Value2: 16V; TaMin_C: -55; TaMax_C: 125
C39 C44 = 08055A331KAT2A: CAP, CERM, 330 pF, 50 V, +/- 10%, C0G/NP0, 0805; Manufacturer: AVX; Polarized: N; CompType: Capacitor; Value: 330pF; U/M: EA; Cap_F: 0.00000000033; Tolerance_%: 10; ESR_ohm: 0.189; Value1: 0.189 ohm; VDC_V: 50; Value2: 50V; TaMin_C: -55; TaMax_C: 125; Cap_Case: 0805
C45 C49 C50 C52 = GMK325AB7106MM-T: as C80 on sheet TIDA-00810_POWER SUPPLY
C46 C48 C51 C53 = C0603C104K5RACTU: as C79 on sheet TIDA-00810_POWER SUPPLY
C47 = C2012X5R1H475K125AB: as C78 on sheet TIDA-00810_POWER SUPPLY
C110-C113 = 06033C101KAT2A: CAP, CERM, 100 pF, 25 V, +/- 10%, X7R, 0603; Manufacturer: AVX; Polarized: N; CompType: Capacitor; Value: 100pF; U/M: EA; Cap_F: 0.0000000001; Tolerance_%: 10; Value1: Unknown; VDC_V: 25; Value2: 25V; TaMin_C: -55; TaMax_C: 125; AEC Category: Q200
D1-D8 = BAV99WT1G: Diode, P-N, 70V, 0.2A, SOT-323; Manufacturer: Diodes Inc
D9 D12 = MBR0520LT1G: Diode, Schottky, 20V, 0.5A, SOD-123; Manufacturer: Diodes Inc; U/M: EA; Vf_V: 0.385; Value2: 0.385V; Io_A: 0.5; Vr_V: 20; TJmax_C: 125; RJC_CperW: 150
D10 = MMSZ5232B-7-F: as D15 on sheet TIDA-00810_POWER SUPPLY
D11 = LED_LG L29K-G2J1-24-Z: as D16 on sheet TIDA-00810_POWER SUPPLY
D21 D22 = PESD3V3L1BA: DIODE, TVS, BIDIRECTIONAL, 3.3VWM, 26VC, SOD323; Manufacturer: NXP Semiconductor; SymbolCreator: x0199378
J3 J4 = ED120/2DS: as J13 on sheet TIDA-00810_POWER SUPPLY
L3 = MMZ1608B102CTA00: as L4 on sheet TIDA-00810_POWER SUPPLY
R50 R65 = CRCW0603160KFKEA: RES, 160 k, 1%, 0.1 W, 0603; Manufacturer: Vishay-Dale; CompType: Resistor; Value: 160k; Res_ohm: 160000; Tolerance_%: 1; Power_W: 0.1; Value2: 0.1W; VDC_V: 75; TempCo: 100 ppm/C; U/M: EA
R51-R53 R61-R63 = ERJ-8ENF3323V: RES, 332 k, 1%, 0.25 W, 1206; Manufacturer: Panasonic; CompType: Resistor; Value: 332k; Res_ohm: 332000; Tolerance_%: 1; Power_W: 0.25; Value2: 0.25W; VDC_V: 200; TempCo: 100 ppm/C; EIA_Code: E96; U/M: EA
R54 R60 R64 R71 = RC0603FR-0712RL: RES, 12.0, 1%, 0.1 W, 0603; Manufacturer: Yageo America; CompType: Resistor; Value: 12.0; Res_ohm: 12; Value_Code: 12R0; Tolerance_%: 1; Power_W: 0.1; Value2: 0.1W; VDC_V: 150; TempCo: 200 ppm/C; U/M: EA
R55 R56 R67 R68 R180 R181 R184 R185 = CRCW0603649RFKEA: RES, 649, 1%, 0.1 W, 0603; Manufacturer: Vishay-Dale; CompType: Resistor; Value: 649; Value_Code: 649R; Tolerance_%: 1; Power_W: 0.1; Value2: 0.1W; VDC_V: 75; TempCo: 100 ppm/C; EIA_Code: E96; U/M: EA; AEC Category: Q200
R57 R58 R66 R69 = CRCW0603100RFKEA: RES, 100 ohm, 1%, 0.1W, 0603; Manufacturer: Vishay-Dale; CompType: Resistor; Value_Code: 100R; Tolerance_%: 1; Power_W: 0.1; VDC_V: 75; TempCo: 100 ppm/C; EIA_Code: E96; U/M: EA
R59 R70 R183 = CRCW08050000Z0EA: RES, 0 ohm, 5%, 0.125W, 0805; Manufacturer: Vishay-Dale; CompType: Resistor; Value_Code: 0000; Tolerance_%: 5; Power_W: 0.125; VDC_V: 150; TempCo: 200 ppm/C; EIA_Code: E24; U/M: EA
R72 R182 = CRCW06030000Z0EA: as R134 on sheet TIDA-00810_POWER SUPPLY
R73 = CRCW06033K90JNEA: as R135 on sheet TIDA-00810_POWER SUPPLY
T1 = 750313734: Transformer, 340 uH, TH; Manufacturer: Wurth Elektronik; SymbolCreator: Altium; Value: 340uH; Lp: 340; DCR_ohm: 0.419
TP9 TP10 = PogoPad: as TP23 on sheet TIDA-00810_POWER SUPPLY
U6 U7 = AMC1200BDWV: Fully-Differential Isolation Amplifier, DWV0008A; Manufacturer: Texas Instruments; SymbolCreator: a0411947; CompType: IC; U/M: EA
U8 = TLV70450DBVR: as U14 on sheet TIDA-00810_POWER SUPPLY
U9 = SN6501DBVR: Transformer Driver for Isolated Power Supplies, DBV0005A; Alternate PartNumber: SN6501DBVT; Manufacturer: Texas Instruments; SymbolCreator: a0411947; CompType: IC; U/M: EA

## Sheet TIDA-00810_OP-AMP.SchDoc: OP-AMP
size 431 x 279 mm; Date: Not shown in title block; ApprovedBy: Not shown in title block; CheckedBy: Not shown in title block; Author: Not shown in title block; CompanyName: Not shown in title block; DrawnBy: Sreenivasa; Engineer: Not shown in title block; Organization: Not shown in title block; Address1: Not shown in title block; Address2: Not shown in title block; Address3: Not shown in title block; Address4: Not shown in title block; DocumentNumber: 1; Revision: Use project parameter SCH_Rev; SheetNumber: 5; SheetTotal: 10; PageSetup: Record=PageOptions¦CenterHorizontal=True¦CenterVertical=True¦PrintScale=1.00¦XCorrection=1.00¦YCorrection=1.00¦PrintKind=0¦BorderSize=5000000¦LeftOffset=0¦BottomOffset=0¦Orientation=2¦PaperLength=1000¦PaperWidth=1000¦Scale=100¦PaperSource=15¦PrintQuality=600¦MediaType=1¦DitherType=10¦PaperKind=Letter¦PrintScaleMode=1
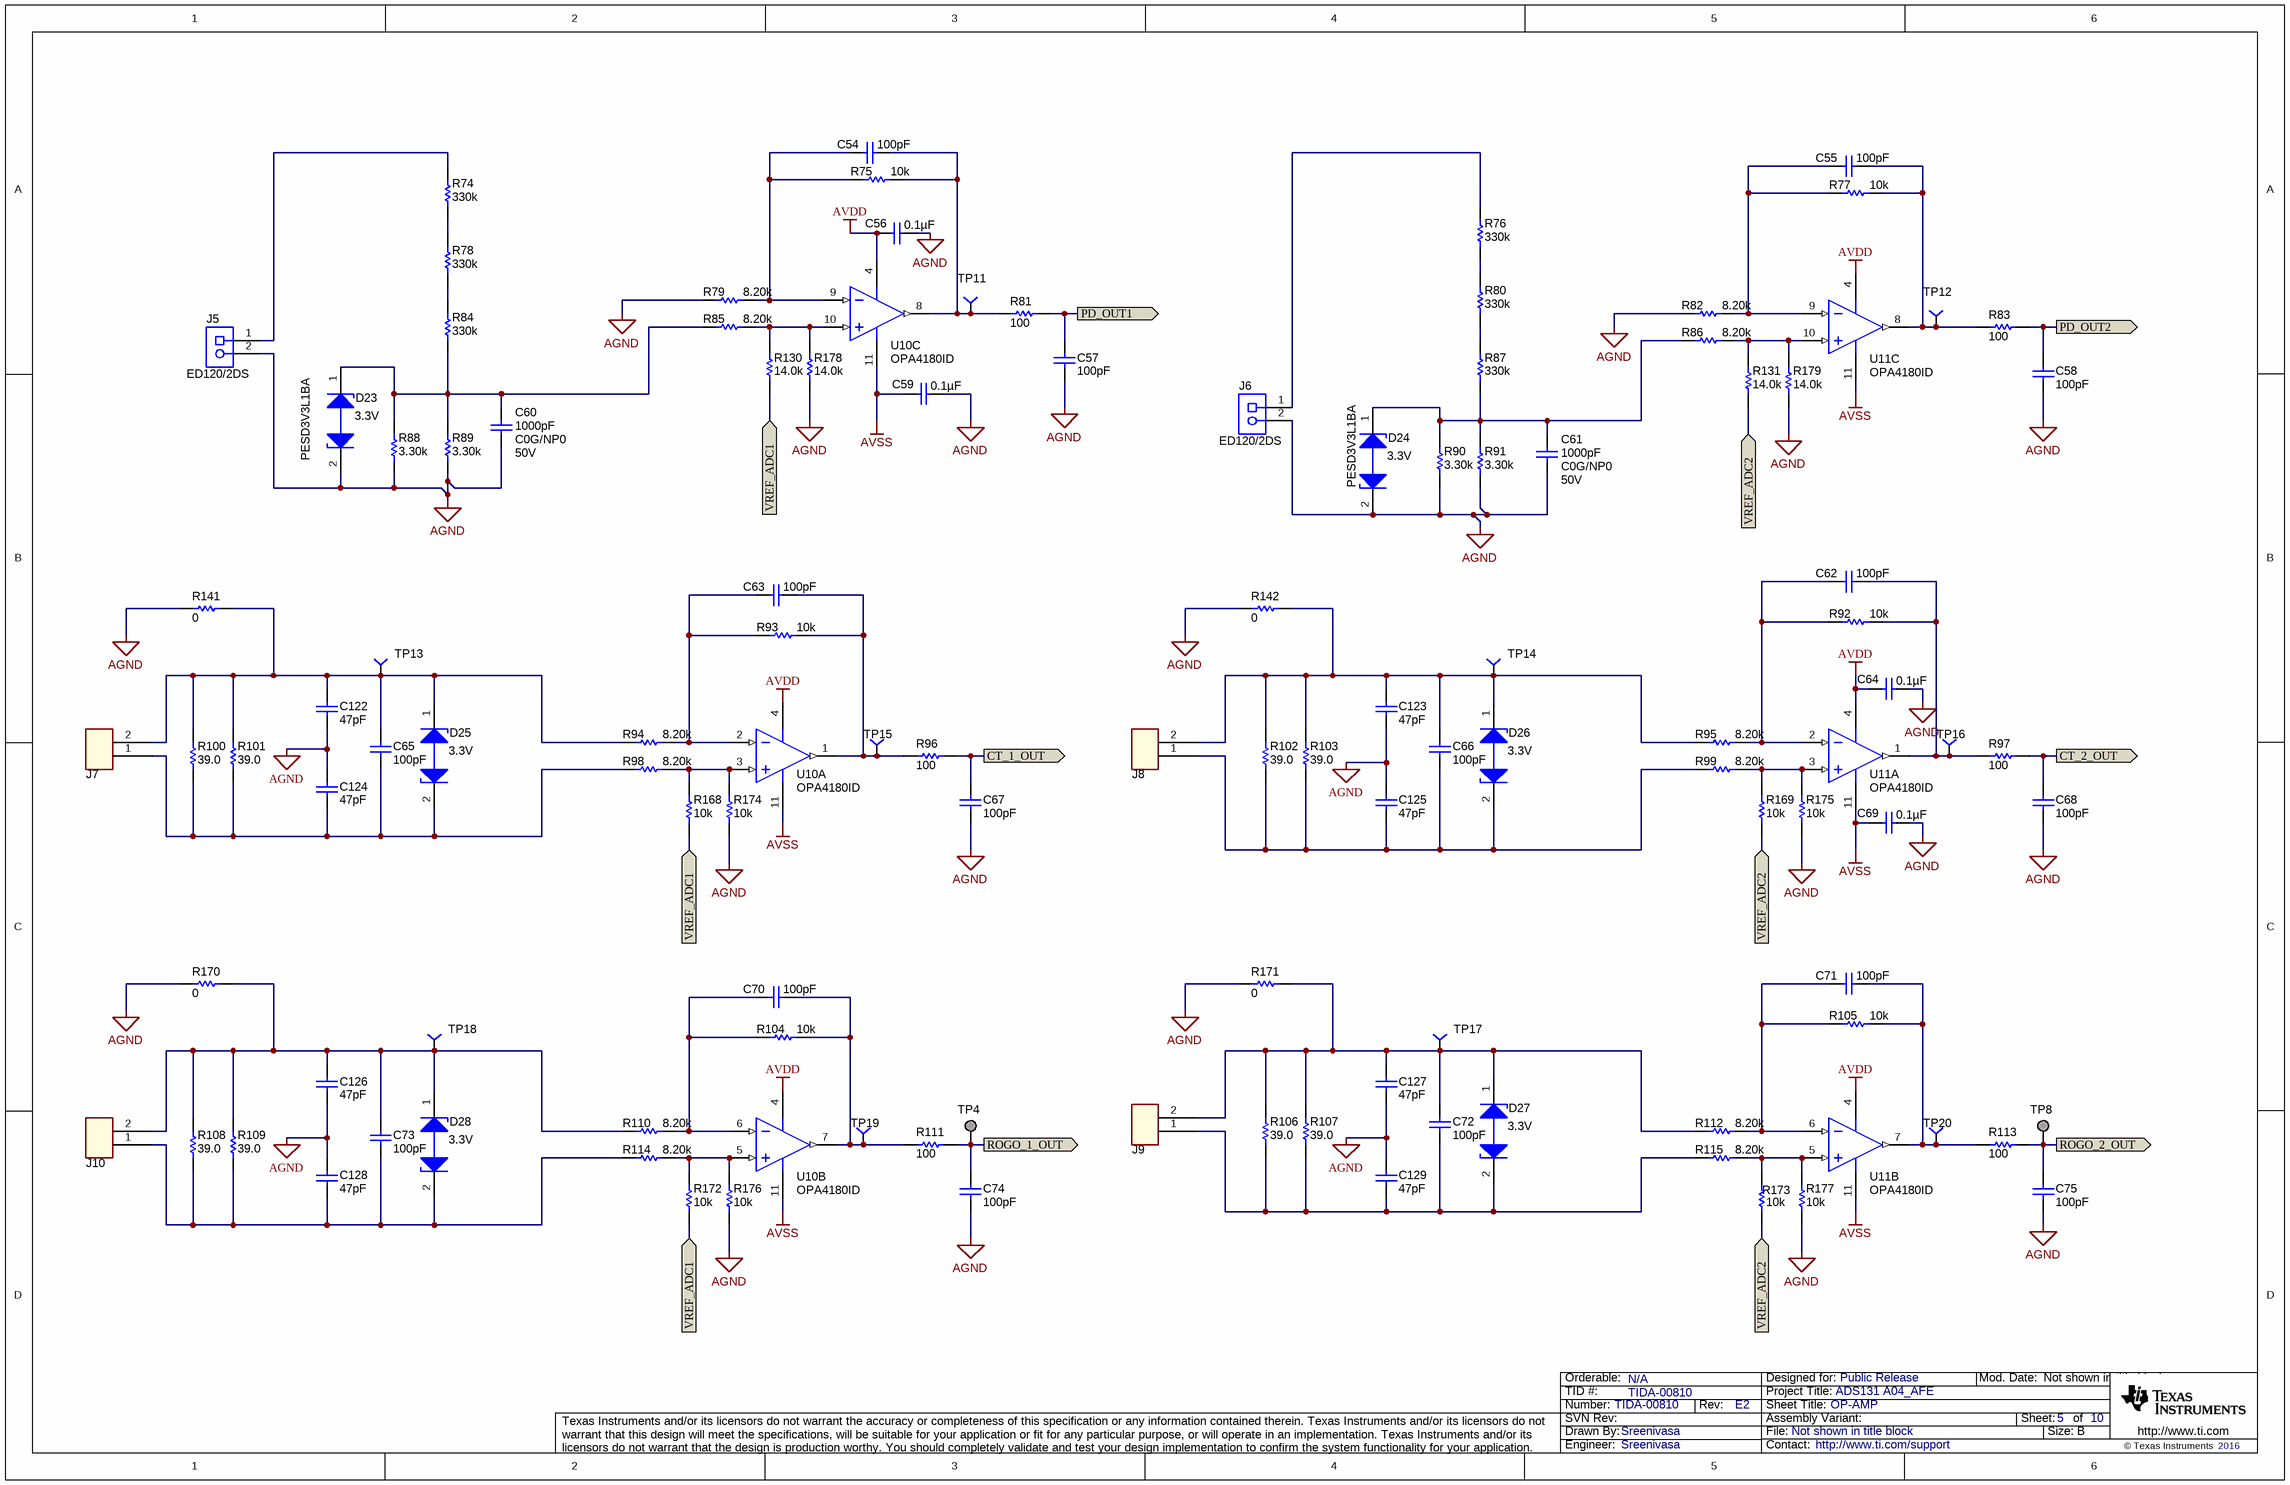
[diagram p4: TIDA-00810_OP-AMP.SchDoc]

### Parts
C54  ValueDisplayed: 100pF  [0603]  (hidden comment: 06033C101KAT2A)
C55  ValueDisplayed: 100pF  [0603]  (hidden comment: 06033C101KAT2A)
C56  ValueDisplayed: 0.1µF  [0603]  (hidden comment: 06033C104JAT2A)
C57  ValueDisplayed: 100pF  [0603]  (hidden comment: 06033C101KAT2A)
C58  ValueDisplayed: 100pF  [0603]  (hidden comment: 06033C101KAT2A)
C59  ValueDisplayed: 0.1µF  [0603]  (hidden comment: 06033C104JAT2A)
C60  ValueDisplayed: 1000pF  Value2: 50V  TempCo: C0G/NP0  [0603]  (hidden comment: C1608C0G1H102J)
C61  ValueDisplayed: 1000pF  Value2: 50V  TempCo: C0G/NP0  [0603]  (hidden comment: C1608C0G1H102J)
C62  ValueDisplayed: 100pF  [0603]  (hidden comment: 06033C101KAT2A)
C63  ValueDisplayed: 100pF  [0603]  (hidden comment: 06033C101KAT2A)
C64  ValueDisplayed: 0.1µF  [0603]  (hidden comment: 06033C104JAT2A)
C65  ValueDisplayed: 100pF  [0603]  (hidden comment: 06033C101KAT2A)
C66  ValueDisplayed: 100pF  [0603]  (hidden comment: 06033C101KAT2A)
C67  ValueDisplayed: 100pF  [0603]  (hidden comment: 06033C101KAT2A)
C68  ValueDisplayed: 100pF  [0603]  (hidden comment: 06033C101KAT2A)
C69  ValueDisplayed: 0.1µF  [0603]  (hidden comment: 06033C104JAT2A)
C70  ValueDisplayed: 100pF  [0603]  (hidden comment: 06033C101KAT2A)
C71  ValueDisplayed: 100pF  [0603]  (hidden comment: 06033C101KAT2A)
C72  ValueDisplayed: 100pF  [0603]  (hidden comment: 06033C101KAT2A)
C73  ValueDisplayed: 100pF  [0603]  (hidden comment: 06033C101KAT2A)
C74  ValueDisplayed: 100pF  [0603]  (hidden comment: 06033C101KAT2A)
C75  ValueDisplayed: 100pF  [0603]  (hidden comment: 06033C101KAT2A)
C122  ValueDisplayed: 47pF  [0805_HV]  (hidden comment: CC0805JRNP09BN470)
C123  ValueDisplayed: 47pF  [0805_HV]  (hidden comment: CC0805JRNP09BN470)
C124  ValueDisplayed: 47pF  [0805_HV]  (hidden comment: CC0805JRNP09BN470)
C125  ValueDisplayed: 47pF  [0805_HV]  (hidden comment: CC0805JRNP09BN470)
C126  ValueDisplayed: 47pF  [0805_HV]  (hidden comment: CC0805JRNP09BN470)
C127  ValueDisplayed: 47pF  [0805_HV]  (hidden comment: CC0805JRNP09BN470)
C128  ValueDisplayed: 47pF  [0805_HV]  (hidden comment: CC0805JRNP09BN470)
C129  ValueDisplayed: 47pF  [0805_HV]  (hidden comment: CC0805JRNP09BN470)
D23  PESD3V3L1BA  value 3.3V  [DIO_SOD323]
D24  PESD3V3L1BA  value 3.3V  [DIO_SOD323]
D25  value 3.3V  [DIO_SOD323]  (hidden comment: PESD3V3L1BA)
D26  value 3.3V  [DIO_SOD323]  (hidden comment: PESD3V3L1BA)
D27  value 3.3V  [DIO_SOD323]  (hidden comment: PESD3V3L1BA)
D28  value 3.3V  [DIO_SOD323]  (hidden comment: PESD3V3L1BA)
J5  ED120/2DS  [CONN_ED120-2DS]
J6  ED120/2DS  [CONN_ED120-2DS]
J7  CON-OSTVN02A150  [CN2_MTB_P100_PD80_D1.1_S5.54X6.5_STACK]  (value not drawn)
J8  CON-OSTVN02A150  [CN2_MTB_P100_PD80_D1.1_S5.54X6.5_STACK]  (value not drawn)
J9  CON-OSTVN02A150  [CN2_MTB_P100_PD80_D1.1_S5.54X6.5_STACK]  (value not drawn)
J10  CON-OSTVN02A150  [CN2_MTB_P100_PD80_D1.1_S5.54X6.5_STACK]  (value not drawn)
R74  ValueDisplayed: 330k  [1206]  (hidden comment: RC1206FR-07330KL)
R75  value 10k  [0603]  (hidden comment: CRCW060310K0FKEA)
R76  ValueDisplayed: 330k  [1206]  (hidden comment: RC1206FR-07330KL)
R77  value 10k  [0603]  (hidden comment: CRCW060310K0FKEA)
R78  ValueDisplayed: 330k  [1206]  (hidden comment: RC1206FR-07330KL)
R79  ValueDisplayed: 8.20k  [0603]  (hidden comment: RC0603FR-078K2L)
R80  ValueDisplayed: 330k  [1206]  (hidden comment: RC1206FR-07330KL)
R81  value 100  [0603]  (hidden comment: CRCW0603100RFKEA)
R82  ValueDisplayed: 8.20k  [0603]  (hidden comment: RC0603FR-078K2L)
R83  value 100  [0603]  (hidden comment: CRCW0603100RFKEA)
R84  ValueDisplayed: 330k  [1206]  (hidden comment: RC1206FR-07330KL)
R85  ValueDisplayed: 8.20k  [0603]  (hidden comment: RC0603FR-078K2L)
R86  ValueDisplayed: 8.20k  [0603]  (hidden comment: RC0603FR-078K2L)
R87  ValueDisplayed: 330k  [1206]  (hidden comment: RC1206FR-07330KL)
R88  ValueDisplayed: 3.30k  [0603]  (hidden comment: RC0603FR-073K3L)
R89  ValueDisplayed: 3.30k  [0603]  (hidden comment: RC0603FR-073K3L)
R90  ValueDisplayed: 3.30k  [0603]  (hidden comment: RC0603FR-073K3L)
R91  ValueDisplayed: 3.30k  [0603]  (hidden comment: RC0603FR-073K3L)
R92  value 10k  [0603]  (hidden comment: CRCW060310K0FKEA)
R93  value 10k  [0603]  (hidden comment: CRCW060310K0FKEA)
R94  ValueDisplayed: 8.20k  [0603]  (hidden comment: RC0603FR-078K2L)
R95  ValueDisplayed: 8.20k  [0603]  (hidden comment: RC0603FR-078K2L)
R96  value 100  [0603]  (hidden comment: CRCW0603100RFKEA)
R97  value 100  [0603]  (hidden comment: CRCW0603100RFKEA)
R98  ValueDisplayed: 8.20k  [0603]  (hidden comment: RC0603FR-078K2L)
R99  ValueDisplayed: 8.20k  [0603]  (hidden comment: RC0603FR-078K2L)
R100  ValueDisplayed: 39.0  [0603]  (hidden comment: RC0603FR-0739RL)
R101  ValueDisplayed: 39.0  [0603]  (hidden comment: RC0603FR-0739RL)
R102  ValueDisplayed: 39.0  [0603]  (hidden comment: RC0603FR-0739RL)
R103  ValueDisplayed: 39.0  [0603]  (hidden comment: RC0603FR-0739RL)
R104  value 10k  [0603]  (hidden comment: CRCW060310K0FKEA)
R105  value 10k  [0603]  (hidden comment: CRCW060310K0FKEA)
R106  ValueDisplayed: 39.0  [0603]  (hidden comment: RC0603FR-0739RL)
R107  ValueDisplayed: 39.0  [0603]  (hidden comment: RC0603FR-0739RL)
R108  ValueDisplayed: 39.0  [0603]  (hidden comment: RC0603FR-0739RL)
R109  ValueDisplayed: 39.0  [0603]  (hidden comment: RC0603FR-0739RL)
R110  ValueDisplayed: 8.20k  [0603]  (hidden comment: RC0603FR-078K2L)
R111  value 100  [0603]  (hidden comment: CRCW0603100RFKEA)
R112  ValueDisplayed: 8.20k  [0603]  (hidden comment: RC0603FR-078K2L)
R113  value 100  [0603]  (hidden comment: CRCW0603100RFKEA)
R114  ValueDisplayed: 8.20k  [0603]  (hidden comment: RC0603FR-078K2L)
R115  ValueDisplayed: 8.20k  [0603]  (hidden comment: RC0603FR-078K2L)
R130  ValueDisplayed: 14.0k  [0603]  (hidden comment: CRCW060314K0FKEA)
R131  ValueDisplayed: 14.0k  [0603]  (hidden comment: CRCW060314K0FKEA)
R141  ValueDisplayed: 0  [0603]  (hidden comment: RC0603JR-070RL)
R142  ValueDisplayed: 0  [0603]  (hidden comment: RC0603JR-070RL)
R168  value 10k  [0603]  (hidden comment: CRCW060310K0FKEA)
R169  value 10k  [0603]  (hidden comment: CRCW060310K0FKEA)
R170  ValueDisplayed: 0  [0603]  (hidden comment: RC0603JR-070RL)
R171  ValueDisplayed: 0  [0603]  (hidden comment: RC0603JR-070RL)
R172  value 10k  [0603]  (hidden comment: CRCW060310K0FKEA)
R173  value 10k  [0603]  (hidden comment: CRCW060310K0FKEA)
R174  value 10k  [0603]  (hidden comment: CRCW060310K0FKEA)
R175  value 10k  [0603]  (hidden comment: CRCW060310K0FKEA)
R176  value 10k  [0603]  (hidden comment: CRCW060310K0FKEA)
R177  value 10k  [0603]  (hidden comment: CRCW060310K0FKEA)
R178  ValueDisplayed: 14.0k  [0603]  (hidden comment: CRCW060314K0FKEA)
R179  ValueDisplayed: 14.0k  [0603]  (hidden comment: CRCW060314K0FKEA)
TP4  Suggest using a net name here  [Keystone1573-2]  (value not drawn)
TP8  Suggest using a net name here  [Keystone1573-2]  (value not drawn)
TP11  TP-040_RND  [TP_H045P075]  (value not drawn)
TP12  TP-040_RND  [TP_H045P075]  (value not drawn)
TP13  TP-040_RND  [TP_H045P075]  (value not drawn)
TP14  TP-040_RND  [TP_H045P075]  (value not drawn)
TP15  TP-040_RND  [TP_H045P075]  (value not drawn)
TP16  TP-040_RND  [TP_H045P075]  (value not drawn)
TP17  TP-040_RND  [TP_H045P075]  (value not drawn)
TP18  TP-040_RND  [TP_H045P075]  (value not drawn)
TP19  TP-040_RND  [TP_H045P075]  (value not drawn)
TP20  TP-040_RND  [TP_H045P075]  (value not drawn)
U10  OPA4180ID  [D0014A_N]  (parts A,B,C of 4)
U11  OPA4180ID  [D0014A_N]  (parts A,B,C of 4)

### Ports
CT_1_OUT (out), CT_2_OUT (out), PD_OUT1 (out), PD_OUT2 (out), ROGO_1_OUT (out), ROGO_2_OUT (out), VREF_ADC1 (in), VREF_ADC2 (in)

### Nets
AGND: C56.1 C57.2 C58.2 C59.1 C60.1 C61.1 C64.1 C67.2 C68.2 C69.1 C74.2 C75.2 C122.2 C123.2 C124.1 C125.1 C126.2 C127.2 C128.1 C129.1 D23.2(K) D24.2(K) J5.2 J6.2 R79.2 R82.2 R88.1 R89.1 R90.1 R91.1 R141.2 R142.2 R170.2 R171.2 R174.1 R175.1 R176.1 R177.1 R178.1 R179.1
AVDD: C56.2 C64.2 U10.4(V+) U11.4(V+)
AVSS: C59.2 C69.2 U10.11(V-) U11.11(V-)
CT_1_OUT: C67.1 R96.2 ; port CT_1_OUT
CT_2_OUT: C68.1 R97.2 ; port CT_2_OUT
PD_OUT1: C57.1 R81.2 ; port PD_OUT1
PD_OUT2: C58.1 R83.2 ; port PD_OUT2
ROGO_1_OUT: C74.1 R111.2 TP4.1 ; port ROGO_1_OUT
ROGO_2_OUT: C75.1 R113.2 TP8.1 ; port ROGO_2_OUT
VREF_ADC1: R130.1 R168.1 R172.1 ; port VREF_ADC1
VREF_ADC2: R131.1 R169.1 R173.1 ; port VREF_ADC2
NetC54_1: C54.1 R75.2 R79.1 U10.9(IN_C-)
NetC54_2: C54.2 R75.1 R81.1 TP11.1 U10.8(OUT_C)
NetC55_1: C55.1 R77.2 R82.1 U11.9(IN_C-)
NetC55_2: C55.2 R77.1 R83.1 TP12.1 U11.8(OUT_C)
NetC60_2: C60.2 D23.1(K) R84.1 R85.2 R88.2 R89.2
NetC61_2: C61.2 D24.1(K) R86.2 R87.1 R90.2 R91.2
NetC62_1: C62.1 R92.2 R95.1 U11.2(IN_A-)
NetC62_2: C62.2 R92.1 R97.1 TP16.1 U11.1(OUT_A)
NetC63_1: C63.1 R93.2 R94.1 U10.2(IN_A-)
NetC63_2: C63.2 R93.1 R96.1 TP15.1 U10.1(OUT_A)
NetC65_1: C65.1 C122.1 D25.1(K) J7.2 R94.2 R100.2 R101.2 R141.1 TP13.1
NetC65_2: C65.2 C124.2 D25.2(K) J7.1 R98.2 R100.1 R101.1
NetC66_1: C66.1 C123.1 D26.1(K) J8.2 R95.2 R102.2 R103.2 R142.1 TP14.1
NetC66_2: C66.2 C125.2 D26.2(K) J8.1 R99.2 R102.1 R103.1
NetC70_1: C70.1 R104.2 R110.1 U10.6(IN_B-)
NetC70_2: C70.2 R104.1 R111.1 TP19.1 U10.7(OUT_B)
NetC71_1: C71.1 R105.2 R112.1 U11.6(IN_B-)
NetC71_2: C71.2 R105.1 R113.1 TP20.1 U11.7(OUT_B)
NetC72_1: C72.1 C127.1 D27.1(K) J9.2 R106.2 R107.2 R112.2 R171.1 TP17.1
NetC72_2: C72.2 C129.2 D27.2(K) J9.1 R106.1 R107.1 R115.2
NetC73_1: C73.1 C126.1 D28.1(K) J10.2 R108.2 R109.2 R110.2 R170.1 TP18.1
NetC73_2: C73.2 C128.2 D28.2(K) J10.1 R108.1 R109.1 R114.2
NetJ5_1: J5.1 R74.2
NetJ6_1: J6.1 R76.2
NetR74_1: R74.1 R78.2
NetR76_1: R76.1 R80.2
NetR78_1: R78.1 R84.2
NetR80_1: R80.1 R87.2
NetR85_1: R85.1 R130.2 R178.2 U10.10(IN_C+)
NetR86_1: R86.1 R131.2 R179.2 U11.10(IN_C+)
NetR98_1: R98.1 R168.2 R174.2 U10.3(IN_A+)
NetR99_1: R99.1 R169.2 R175.2 U11.3(IN_A+)
NetR114_1: R114.1 R172.2 R176.2 U10.5(IN_B+)
NetR115_1: R115.1 R173.2 R177.2 U11.5(IN_B+)

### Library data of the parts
C54 C55 C62 C63 C65 C66 C70-C73 = 06033C101KAT2A: CAP, CERM, 100pF, 25V, +/-10%, X7R, 0603; Manufacturer: AVX; Polarized: N; CompType: Capacitor; U/M: EA; Cap_F: 0.0000000001; Tolerance_%: 10; Value1: Unknown; VDC_V: 25; TaMin_C: -55; TaMax_C: 125
C56 C59 C64 C69 = 06033C104JAT2A: as C35 on sheet TIDA-00810_Isolation Amplifier
C57 C58 C67 C68 C74 C75 = 06033C101KAT2A: as C110 on sheet TIDA-00810_Isolation Amplifier
C60 C61 = C1608C0G1H102J: CAP, CERM, 1000pF, 50V, +/-5%, C0G/NP0, 0603; Manufacturer: TDK; Polarized: N; CompType: Capacitor; U/M: EA; Cap_F: 0.000000001; Tolerance_%: 5; ESR_Ohm: 0.0563; Value1: 0.0563 ohm; VDC_V: 50; TaMin_C: -55; TaMax_C: 125
C122-C129 = CC0805JRNP09BN470: CAP, CERM, 47 pF, 50 V, +/- 5%, C0G/NP0, 0805; Manufacturer: Yageo America; Polarized: N; CompType: Capacitor; Value: 47pF; U/M: EA; Cap_F: 0.000000000047; Tolerance_%: 5; Value1: Unknown; VDC_V: 50; Value2: 50V; TaMin_C: -55; TaMax_C: 125; Cap_Case: 0805; AEC Category: Q200
D23-D28 = PESD3V3L1BA: as D21 on sheet TIDA-00810_Isolation Amplifier
J5 J6 = ED120/2DS: as J13 on sheet TIDA-00810_POWER SUPPLY
J7-J10 = CON-OSTVN02A150: Terminal Block, 4x1, 2.54mm, TH; Manufacturer: On Shore Technology Inc; SymbolCreator: x0120606
R74 R76 R78 R80 R84 R87 = RC1206FR-07330KL: RES, 330 k, 1%, 0.25 W, 1206; Manufacturer: Yageo America; CompType: Resistor; Value: 330k; Res_ohm: 330000; Tolerance_%: 1; Power_W: 0.25; Value2: 0.25W; VDC_V: 200; TempCo: 100 ppm/C; U/M: EA
R75 R77 R92 R93 R104 R105 R168 R169 R172-R177 = RNCF0603TKY10K0: RES, 10.0k ohm, 1%, 0.1W, 0603; Manufacturer: Stackpole Electronics Inc; CompType: Resistor; Res_ohm: 10000; Value_Code: 10k0; Tolerance_%: 0.01; Value1: 0.01%; Power_W: 0.063; Value2: 0.063W; VDC_V: 50; TempCo: 5 ppm/C; U/M: EA
R79 R82 R85 R86 R94 R95 R98 R99 R110 R112 R114 R115 = RC0603FR-078K2L: RES, 8.20 k, 1%, 0.1 W, 0603; Manufacturer: Yageo America; CompType: Resistor; Value: 8.20k; Res_ohm: 8200; Value_Code: 8k20; Tolerance_%: 1; Power_W: 0.1; Value2: 0.1W; VDC_V: 150; TempCo: 200 ppm/C; U/M: EA; AEC Category: Q200
R81 R83 R96 R97 R111 R113 = CRCW0603100RFKEA: as R57 on sheet TIDA-00810_Isolation Amplifier
R88-R91 = RC0603FR-073K3L: RES, 3.30 k, 1%, 0.1 W, 0603; Manufacturer: Yageo America; CompType: Resistor; Value: 3.30k; Res_ohm: 3300; Value_Code: 3k30; Tolerance_%: 1; Power_W: 0.1; Value2: 0.1W; VDC_V: 150; TempCo: 200 ppm/C; U/M: EA; AEC Category: Q200
R100-R103 R106-R109 = RC0603FR-0739RL: RES, 39.0, 1%, 0.1 W, 0603; Manufacturer: Yageo America; CompType: Resistor; Value: 39.0; Res_ohm: 39; Value_Code: 39R0; Tolerance_%: 1; Power_W: 0.1; Value2: 0.1W; VDC_V: 150; TempCo: 200 ppm/C; U/M: EA; AEC Category: Q200
R130 R131 R178 R179 = CRCW060314K0FKEA: RES, 14.0 k, 1%, 0.1 W, 0603; Manufacturer: Vishay-Dale; CompType: Resistor; Value: 14.0k; Res_ohm: 14000; Value_Code: 14k0; Tolerance_%: 1; Power_W: 0.1; Value2: 0.1W; VDC_V: 75; TempCo: 100 ppm/C; EIA_Code: E96; U/M: EA; AEC Category: Q200
R141 R142 R170 R171 = RC0603JR-070RL: RES, 0, 5%, 0.1 W, 0603; Manufacturer: Yageo America; CompType: Resistor; Value: 0; Value_Code: 0000; Tolerance_%: 5; Power_W: 0.1; Value2: 0.1W; VDC_V: 50; TempCo: 200 ppm/C; EIA_Code: E24; U/M: EA; AEC Category: Q200
TP4 TP8 = 1573-2: Terminal, Turret, TH, Double; Manufacturer: Keystone; CompType: Turret Terminal; U/M: EA
TP11-TP20 = TP-040_RND: Test Point, O.040 Hole; Manufacturer: STD; Value: STD
U10 U11 = OPA4180ID: 0.1 uV/C Drift, Quad, Low Noise, Rail-to-Rail, Zero Drift Operational Amplifier, 4 to 36 V, -40 to 105 degC, 14-pin SOIC (D0014A), Green (RoHS & no Sb/Br); Manufacturer: Texas Instruments; Alternate PartNumber: Equivalent; CMRR(Min)(dB): 104; GBW(Typ)(MHz): 2; IIB(Max)(pA): 1700; Iq per channel(Max)(mA): 0.525; Number of Channels: 4; Offset Drift(Typ)(uV/C): 0.1; Rating: Catalog; Slew Rate(Typ)(V/us): 0.8; Sub Family: Precision Amplifier; Total Supply Voltage(Max)(+5V is 5, +/-5V is 10): 36; Vio (25C)(Max)(mV): 0.075

## Sheet TIDA-00810_Reference.SchDoc: OP-AMP
size 431 x 279 mm; Date: Not shown in title block; ApprovedBy: Not shown in title block; CheckedBy: Not shown in title block; Author: Not shown in title block; CompanyName: Not shown in title block; DrawnBy: Sreenivasa; Engineer: Not shown in title block; Organization: Not shown in title block; Address1: Not shown in title block; Address2: Not shown in title block; Address3: Not shown in title block; Address4: Not shown in title block; DocumentNumber: 1; Revision: Use project parameter SCH_Rev; SheetNumber: 6; SheetTotal: 10; PageSetup: Record=PageOptions¦CenterHorizontal=True¦CenterVertical=True¦PrintScale=1.00¦XCorrection=1.00¦YCorrection=1.00¦PrintKind=0¦BorderSize=5000000¦LeftOffset=0¦BottomOffset=0¦Orientation=2¦PaperLength=1000¦PaperWidth=1000¦Scale=100¦PaperSource=15¦PrintQuality=600¦MediaType=1¦DitherType=10¦PaperKind=Letter¦PrintScaleMode=1
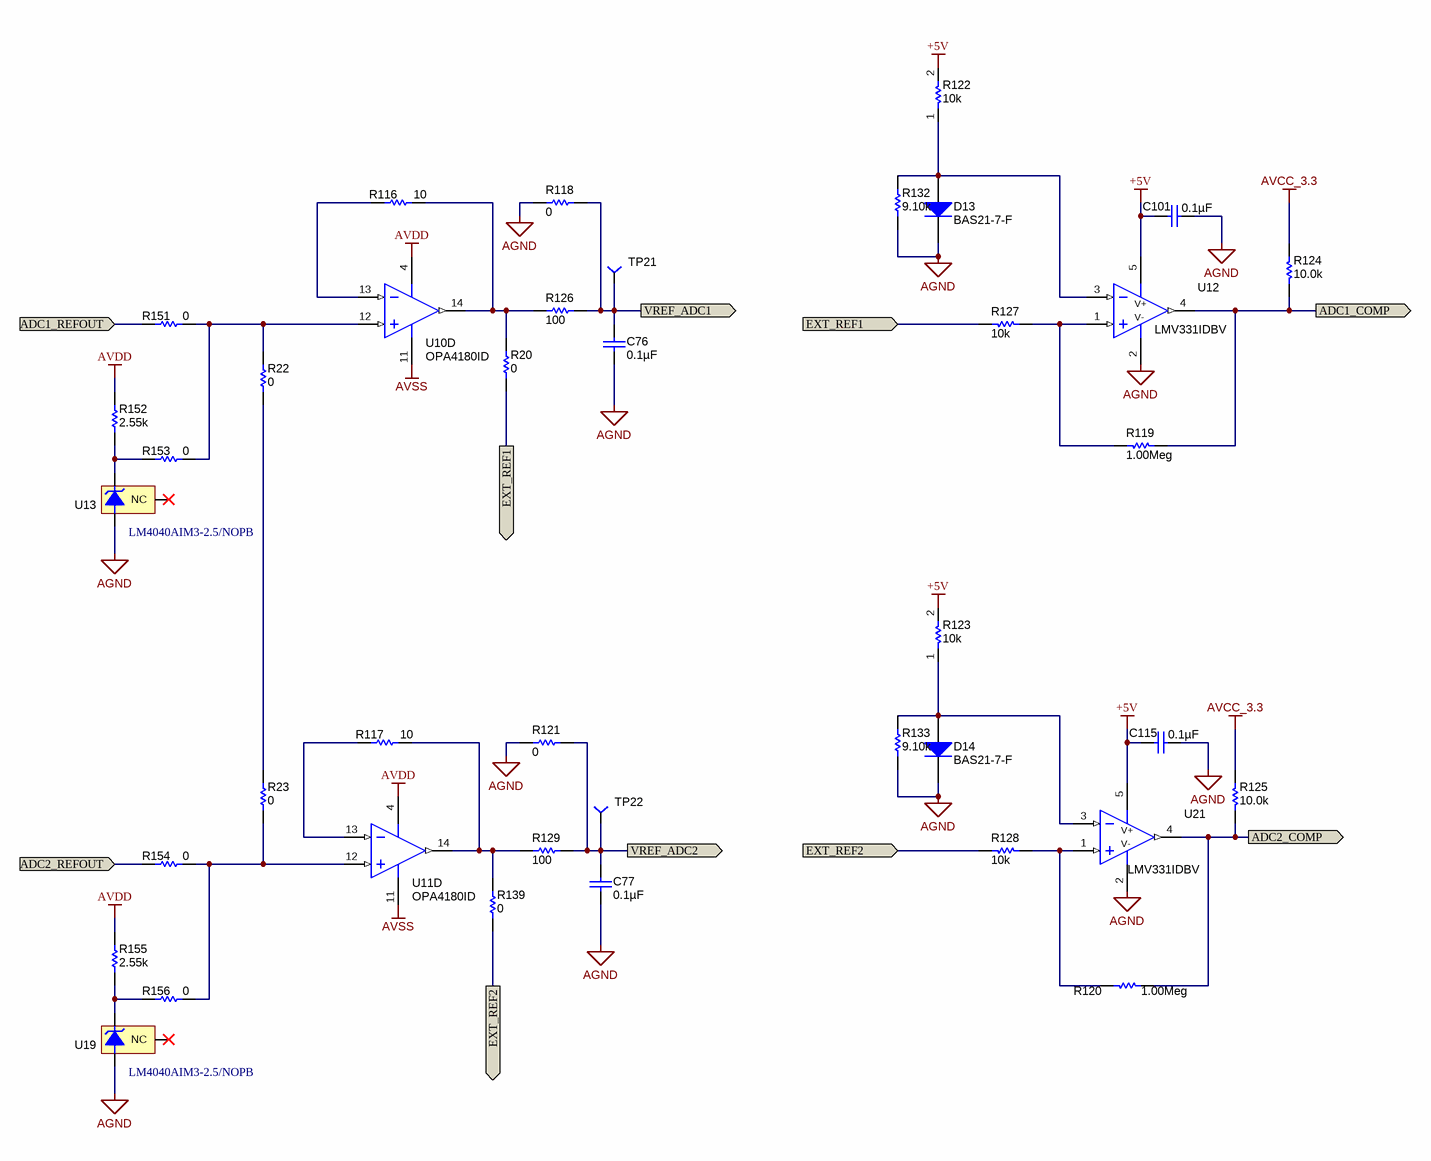
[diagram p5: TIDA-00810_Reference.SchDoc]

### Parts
C76  ValueDisplayed: 0.1µF  [0603]  (hidden comment: 06033C104JAT2A)
C77  ValueDisplayed: 0.1µF  [0603]  (hidden comment: 06033C104JAT2A)
C101  ValueDisplayed: 0.1µF  [0603]  (hidden comment: 06033C104JAT2A)
C115  ValueDisplayed: 0.1µF  [0603]  (hidden comment: 06033C104JAT2A)
D13  BAS21-7-F  [SOT-23]
D14  BAS21-7-F  [SOT-23]
R20  value 0  [0805_HV]  (hidden comment: CRCW08050000Z0EA)
R22  value 0  [0805_HV]  (hidden comment: CRCW08050000Z0EA)
R23  value 0  [0805_HV]  (hidden comment: CRCW08050000Z0EA)
R116  ValueDisplayed: 10  [0603]  (hidden comment: CRCW060310R0JNEA)
R117  ValueDisplayed: 10  [0603]  (hidden comment: CRCW060310R0JNEA)
R118  ValueDisplayed: 0  [0603]  (hidden comment: RC0603JR-070RL)
R119  value 1.00Meg  [0603]  (hidden comment: CRCW06031M00FKEA)
R120  value 1.00Meg  [0603]  (hidden comment: CRCW06031M00FKEA)
R121  ValueDisplayed: 0  [0603]  (hidden comment: RC0603JR-070RL)
R122  value 10k  [0603]  (hidden comment: CRCW060310K0FKEA)
R123  value 10k  [0603]  (hidden comment: CRCW060310K0FKEA)
R124  value 10.0k  [0603]  (hidden comment: CRCW060310K0FKEA)
R125  value 10.0k  [0603]  (hidden comment: CRCW060310K0FKEA)
R126  value 100  [0603]  (hidden comment: CRCW0603100RFKEA)
R127  value 10k  [0603]  (hidden comment: CRCW060310K0FKEA)
R128  value 10k  [0603]  (hidden comment: CRCW060310K0FKEA)
R129  value 100  [0603]  (hidden comment: CRCW0603100RFKEA)
R132  ValueDisplayed: 9.10k  [1206]  (hidden comment: RC1206FR-079K1L)
R133  ValueDisplayed: 9.10k  [1206]  (hidden comment: RC1206FR-079K1L)
R139  value 0  [0805_HV]  (hidden comment: CRCW08050000Z0EA)
R151  value 0  [0805_HV]  (hidden comment: CRCW08050000Z0EA)
R152  ValueDisplayed: 2.55k  [0603]  (hidden comment: CRCW06032K55FKEA)
R153  value 0  [0805_HV]  (hidden comment: CRCW08050000Z0EA)
R154  value 0  [0805_HV]  (hidden comment: CRCW08050000Z0EA)
R155  ValueDisplayed: 2.55k  [0603]  (hidden comment: CRCW06032K55FKEA)
R156  value 0  [0805_HV]  (hidden comment: CRCW08050000Z0EA)
TP21  TP-040_RND  [TP_H045P075]  (value not drawn)
TP22  TP-040_RND  [TP_H045P075]  (value not drawn)
U10  OPA4180ID  [D0014A_N]  (part D of 4)
U11  OPA4180ID  [D0014A_N]  (part D of 4)
U12  LMV331IDBV  [DBV0005A_N]
U13  LM4040AIM3-2.5/NOPB  [MF03A_N]
U19  LM4040AIM3-2.5/NOPB  [MF03A_N]
U21  LMV331IDBV  [DBV0005A_N]

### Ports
ADC1_COMP (out), ADC1_REFOUT (in), ADC2_COMP (out), ADC2_REFOUT (in), EXT_REF1 (in), EXT_REF1 (out), EXT_REF2 (in), EXT_REF2 (out), VREF_ADC1 (out), VREF_ADC2 (out)

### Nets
+5V: C101.2 C115.2 R122.2 R123.2 U12.5(V+) U21.5(V+)
AGND: C76.1 C77.1 C101.1 C115.1 D13.3(K) D14.3(K) R118.2 R121.2 R132.1 R133.1 U12.2(V-) U13.2(-V) U19.2(-V) U21.2(V-)
AVCC_3.3: R124.2 R125.2
AVDD: R152.2 R155.2 U10.4(V+) U11.4(V+)
AVSS: U10.11(V-) U11.11(V-)
ADC1_COMP: R119.1 R124.1 U12.4(OUT) ; port ADC1_COMP
ADC1_REFOUT: R151.1 ; port ADC1_REFOUT
ADC2_COMP: R120.2 R125.1 U21.4(OUT) ; port ADC2_COMP
ADC2_REFOUT: R154.1 ; port ADC2_REFOUT
EXT_REF1: R20.1 R127.1 ; port EXT_REF1
EXT_REF2: R128.1 R139.1 ; port EXT_REF2
VREF_ADC1: C76.2 R118.1 R126.2 TP21.1 ; port VREF_ADC1
VREF_ADC2: C77.2 R121.1 R129.2 TP22.1 ; port VREF_ADC2
NetD13_1: D13.1(A) R122.1 R132.2 U12.3(IN-)
NetD14_1: D14.1(A) R123.1 R133.2 U21.3(IN-)
NetR20_2: R20.2 R116.2 R126.1 U10.14(OUT_D)
NetR22_1: R22.1 R23.2
NetR22_2: R22.2 R151.2 R153.2 U10.12(IN_D+)
NetR23_1: R23.1 R154.2 R156.2 U11.12(IN_D+)
NetR116_1: R116.1 U10.13(IN_D-)
NetR117_1: R117.1 U11.13(IN_D-)
NetR117_2: R117.2 R129.1 R139.2 U11.14(OUT_D)
NetR119_2: R119.2 R127.2 U12.1(IN+)
NetR120_1: R120.1 R128.2 U21.1(IN+)
NetR152_1: R152.1 R153.1 U13.1(+V)
NetR155_1: R155.1 R156.1 U19.1(+V)

Not connected (* = marked no-connect by the designer): U13 3(NC)*; U19 3(NC)*

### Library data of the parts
C76 C77 C101 C115 = 06033C104JAT2A: as C35 on sheet TIDA-00810_Isolation Amplifier
D13 D14 = BAS21-7-F: Diode, Switching, 200V, 0.2A, SOT-23; Manufacturer: Diodes Inc.; U/M: EA; Vf_V: 1.25; Value2: 1.25V; Io_A: 0.2; Vr_V: 200; TJmax_C: 150; RJC_CperW: 500
R20 R22 R23 R139 R151 R153 R154 R156 = CRCW08050000Z0EA: as R59 on sheet TIDA-00810_Isolation Amplifier
R116 R117 = CRCW060310R0JNEA: RES, 10, 5%, 0.1 W, 0603; Manufacturer: Vishay-Dale; CompType: Resistor; Value: 10; Value_Code: 10R0; Tolerance_%: 5; Power_W: 0.1; Value2: 0.1W; VDC_V: 75; TempCo: 200 ppm/C; EIA_Code: E24; U/M: EA
R118 R121 = RC0603JR-070RL: as R141 on sheet TIDA-00810_OP-AMP
R119 R120 = CRCW06031M00FKEA: RES, 1.00Meg ohm, 1%, 0.1W, 0603; Manufacturer: Vishay-Dale; CompType: Resistor; Res_ohm: 1000000; Value_Code: 1M00; Tolerance_%: 1; Power_W: 0.1; VDC_V: 75; TempCo: 100 ppm/C; EIA_Code: E96; U/M: EA
R122 R123 R127 R128 = RNCF0603TKY10K0: as R75 on sheet TIDA-00810_OP-AMP
R124 R125 = CRCW060310K0FKEA: RES, 10.0k ohm, 1%, 0.1W, 0603; Manufacturer: Vishay-Dale; CompType: Resistor; Res_ohm: 10000; Value_Code: 10k0; Tolerance_%: 1; Power_W: 0.1; VDC_V: 75; TempCo: 100 ppm/C; EIA_Code: E96; U/M: EA
R126 R129 = CRCW0603100RFKEA: as R57 on sheet TIDA-00810_Isolation Amplifier
R132 R133 = RC1206FR-079K1L: RES, 9.10 k, 1%, 0.25 W, 1206; Manufacturer: Yageo America; CompType: Resistor; Value: 9.10k; Res_ohm: 9100; Value_Code: 9k10; Tolerance_%: 1; Power_W: 0.25; Value2: 0.25W; VDC_V: 200; TempCo: 100 ppm/C; U/M: EA; AEC Category: Q200
R152 R155 = CRCW06032K55FKEA: RES, 2.55 k, 1%, 0.1 W, 0603; Manufacturer: Vishay-Dale; CompType: Resistor; Value: 2.55k; Res_ohm: 2550; Value_Code: 2k55; Tolerance_%: 1; Power_W: 0.1; Value2: 0.1W; VDC_V: 75; TempCo: 100 ppm/C; EIA_Code: E96; U/M: EA; AEC Category: Q200
TP21 TP22 = TP-040_RND: as TP11 on sheet TIDA-00810_OP-AMP
U10 U11 = OPA4180ID: as U10 on sheet TIDA-00810_OP-AMP
U12 U21 = LMV331IDBV: Single General Purpose Low-Voltage Comparator, DBV0005A; Manufacturer: Texas Instruments; SymbolCreator: a0411595; CompType: OpAmp IC
U13 U19 = LM4040AIM3-2.5/NOPB: Precision Micropower Shunt Voltage Reference, 3-pin SOT-23, Pb-Free; Manufacturer: Texas Instruments; PackageTopMarking: R2A*XTT; PowerWise: N; CompType: Voltage Reference IC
